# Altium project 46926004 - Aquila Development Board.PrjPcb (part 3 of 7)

## Sheet 400_M2_KeyB.SchDoc: Aquila Development Board
size A3; Organization: Toradex Solutions Inc.; Address1: 6415 Northwest Drive; Address2: Mississauga, ON, L4V 1X1; Address3: Canada; SheetNumber: 21; SheetTotal: 34
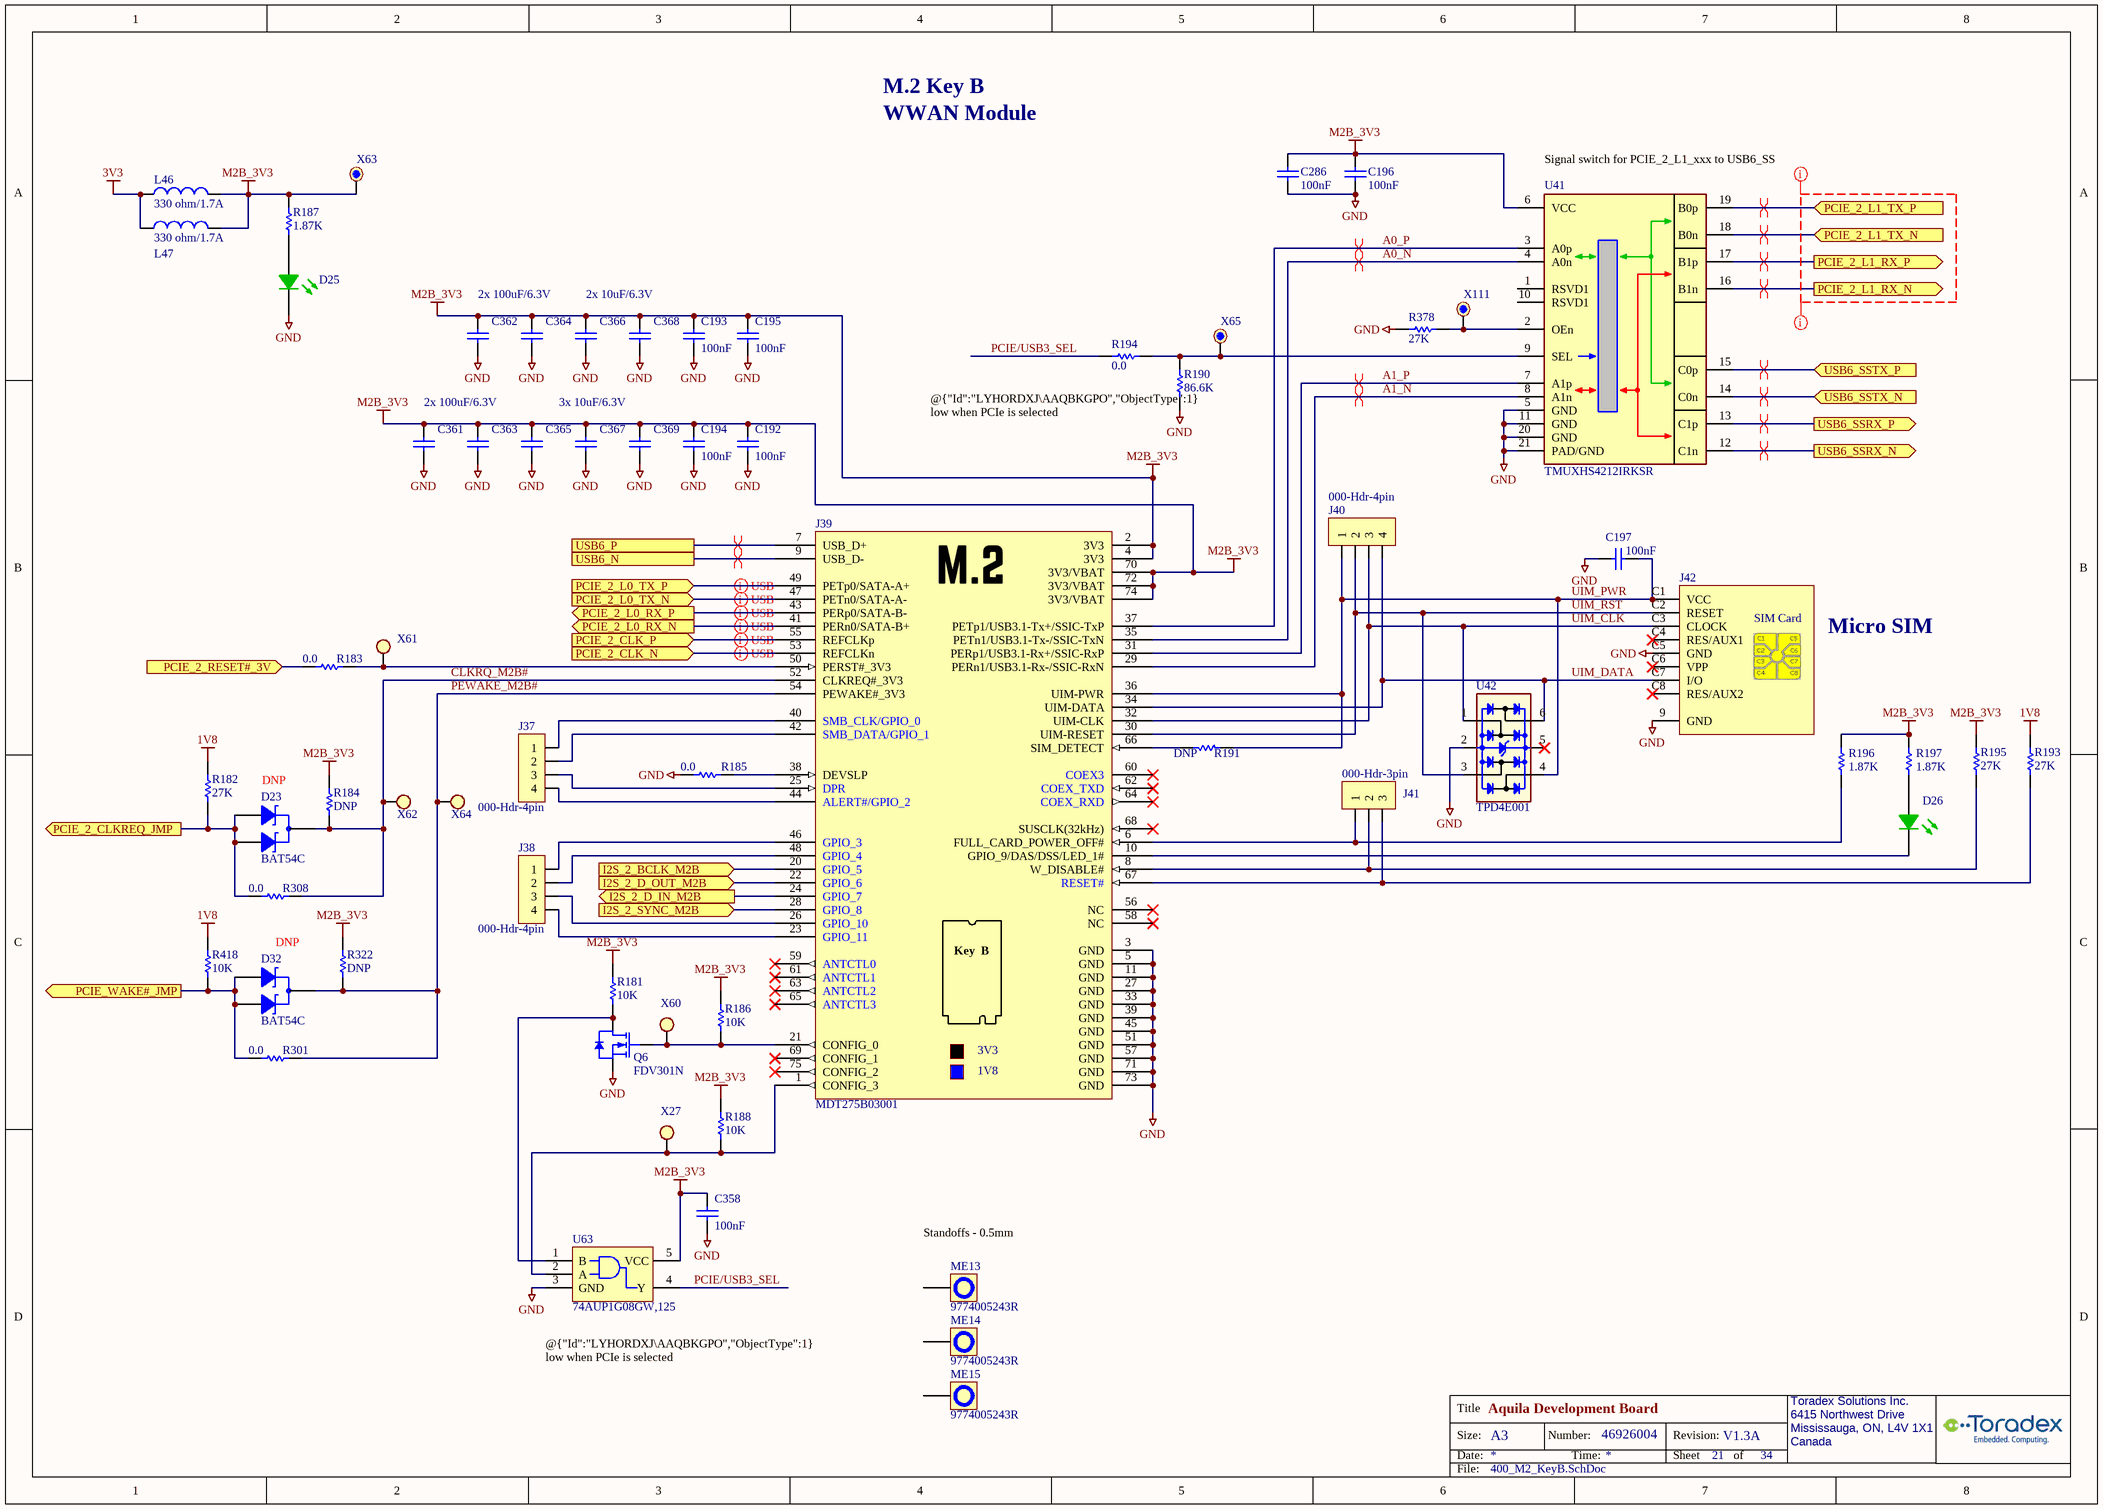
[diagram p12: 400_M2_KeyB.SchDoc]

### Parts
C192  100nF  [C0402_CAPC1005L]
C193  100nF  [C0402_CAPC1005L]
C194  100nF  [C0402_CAPC1005L]
C195  100nF  [C0402_CAPC1005L]
C196  100nF  [C0402_CAPC1005L]
C197  100nF  [C0402_CAPC1005L]
C286  100nF  [C0402_CAPC1005L]
C358  100nF  [C0402_CAPC1005L]
C361  0455-Cap-1206-100uF/6.3V  [C/1206]  (value not drawn)
C362  0455-Cap-1206-100uF/6.3V  [C/1206]  (value not drawn)
C363  0455-Cap-1206-100uF/6.3V  [C/1206]  (value not drawn)
C364  0455-Cap-1206-100uF/6.3V  [C/1206]  (value not drawn)
C365  1646-Cap-0402-10uF/6.3V  [C0402_CAPC1005L]  (value not drawn)
C366  1646-Cap-0402-10uF/6.3V  [C0402_CAPC1005L]  (value not drawn)
C367  1646-Cap-0402-10uF/6.3V  [C0402_CAPC1005L]  (value not drawn)
C368  1646-Cap-0402-10uF/6.3V  [C0402_CAPC1005L]  (value not drawn)
C369  1646-Cap-0402-10uF/6.3V  [C0402_CAPC1005L]  (value not drawn)
D23  BAT54C  [SOT23_M]  (no BOM)
D25  Status  [LED-SMT-0603_APT1608CGCK]  (value not drawn)
D26  Status  [LED-SMT-0603_APT1608CGCK]  (value not drawn)
D32  BAT54C  [SOT23_M]  (no BOM)
J37  000-Hdr-4pin  [HDR1X4]  (no BOM)
J38  000-Hdr-4pin  [HDR1X4]  (no BOM)
J39  MDT275B03001  [AMPHENOL_MDT275B03001_TYPE_3052]
J40  000-Hdr-4pin  [HDR1X4]  (no BOM)
J41  000-Hdr-3pin  [HDR1X3]  (no BOM)
J42  0737-Conn-MicroSIM  [microSD 0787231001]  (value not drawn)
L46  value 330 ohm/1.7A  [C/0603]  (hidden comment: 0405-Fer-0603-330ohm/1.7A)
L47  value 330 ohm/1.7A  [C/0603]  (hidden comment: 0405-Fer-0603-330ohm/1.7A)
ME13  9774005243R  [MECH-WURTH-9774005243R]
ME14  9774005243R  [MECH-WURTH-9774005243R]
ME15  9774005243R  [MECH-WURTH-9774005243R]
Q6  FDV301N  [SOT23]
R181  value 10K  [R0402_RESC1005L]  (hidden comment: 1572-Res-0402-10K)
R182  value 27K  [R0402_RESC1005L]  (hidden comment: 1538-Res-0402-27k)
R183  value 0.0  [R/0603]  (hidden comment: 0195-Res-0603-0.0ohm)
R184  value DNP  [R0402_RESC1005L]  (hidden comment: 0000-Res-0402-DNP)
R185  value 0.0  [R/0603]  (hidden comment: 0195-Res-0603-0.0ohm)
R186  value 10K  [R0402_RESC1005L]  (hidden comment: 1572-Res-0402-10K)
R187  value 1.87K  [R0402_RESC1005L]  (hidden comment: 1536-Res-0402-1.87K)
R188  value 10K  [R0402_RESC1005L]  (hidden comment: 1572-Res-0402-10K)
R190  value 86.6K  [R0402_RESC1005L]  (hidden comment: 1539-Res-0402-86.6k)
R191  value DNP  [R/0603]  (hidden comment: 0000-Res-0603-DNP)
R193  value 27K  [R0402_RESC1005L]  (hidden comment: 1538-Res-0402-27k)
R194  value 0.0  [R/0603]  (hidden comment: 0195-Res-0603-0.0ohm)
R195  value 27K  [R0402_RESC1005L]  (hidden comment: 1538-Res-0402-27k)
R196  value 1.87K  [R0402_RESC1005L]  (hidden comment: 1536-Res-0402-1.87K)
R197  value 1.87K  [R0402_RESC1005L]  (hidden comment: 1536-Res-0402-1.87K)
R301  value 0.0  [R/0603]  (hidden comment: 0195-Res-0603-0.0ohm)
R308  value 0.0  [R/0603]  (hidden comment: 0195-Res-0603-0.0ohm)
R322  value DNP  [R0402_RESC1005L]  (hidden comment: 0000-Res-0402-DNP)
R378  value 27K  [R0402_RESC1005L]  (hidden comment: 1538-Res-0402-27k)
R418  value 10K  [R0402_RESC1005L]  (hidden comment: 1572-Res-0402-10K)
U41  TMUXHS4212IRKSR  [VQFN-20 (4.5x2.5)]
U42  TPD4E001  [SOT23-6]
U63  74AUP1G08GW,125  [SOT353-5N]
X27  000-TestPoint2  [TestPoint_3]  (value not drawn)
X60  000-TestPoint2  [TestPoint_3]  (value not drawn)
X61  000-TestPoint2  [TestPoint_3]  (value not drawn)
X62  000-TestPoint2  [TestPoint_3]  (value not drawn)
X63  000-TestPoint  [TestPoint_1]  (value not drawn)
X64  000-TestPoint2  [TestPoint_3]  (value not drawn)
X65  000-TestPoint  [TestPoint_1]  (value not drawn)
X111  000-TestPoint  [TestPoint_1]  (value not drawn)

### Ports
I2S_2_BCLK_M2B (in), I2S_2_D_IN_M2B (out), I2S_2_D_OUT_M2B (in), I2S_2_SYNC_M2B (in), PCIE_2_CLK_N (in), PCIE_2_CLK_P (in), PCIE_2_CLKREQ_JMP (out), PCIE_2_L0_RX_N (out), PCIE_2_L0_RX_P (out), PCIE_2_L0_TX_N (in), PCIE_2_L0_TX_P (in), PCIE_2_L1_RX_N (out), PCIE_2_L1_RX_P (out), PCIE_2_L1_TX_N (in), PCIE_2_L1_TX_P (in), PCIE_2_RESET#_3V (in), PCIE_WAKE#_JMP (out), USB6_N, USB6_P, USB6_SSRX_N (out), USB6_SSRX_P (out), USB6_SSTX_N (in), USB6_SSTX_P (in)

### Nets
1V8: R182.1 R193.1 R418.2
3V3: L46.1 L47.1
GND: C192.1 C193.1 C194.1 C195.1 C196.2 C197.2 C286.2 C358.1 C361.1 C362.1 C363.1 C364.1 C365.1 C366.1 C367.1 C368.1 C369.1 D25.2(K) J39.3(GND) J39.5(GND) J39.11(GND) J39.27(GND) J39.33(GND) J39.39(GND) J39.45(GND) J39.51(GND) J39.57(GND) J39.71(GND) J39.73(GND) J42.9(GND) J42.C5(GND) Q6.2(S) R185.2 R190.1 R378.1 U41.5(GND) U41.11(GND) U41.20(GND) U41.21(PAD/GND) U42.2 U63.3(GND)
M2B_3V3: C192.2 C193.2 C194.2 C195.2 C196.1 C286.1 C358.2 C361.2 C362.2 C363.2 C364.2 C365.2 C366.2 C367.2 C368.2 C369.2 J39.2(3V3) J39.4(3V3) J39.70(3V3/VBAT) J39.72(3V3/VBAT) J39.74(3V3/VBAT) L46.2 L47.2 R181.2 R184.1 R186.2 R187.2 R188.2 R195.1 R196.2 R197.2 R322.1 U41.6(VCC) U63.5(VCC) X63.1
A0_N: J39.35(PETn1/USB3.1-Tx-/SSIC-TxN) U41.4(A0n)
A0_P: J39.37(PETp1/USB3.1-Tx+/SSIC-TxP) U41.3(A0p)
A1_N: J39.29(PERn1/USB3.1-Rx-/SSIC-RxN) U41.8(A1n)
A1_P: J39.31(PERp1/USB3.1-Rx+/SSIC-RxP) U41.7(A1p)
CLKRQ_M2B#: D23.3(K) J39.52(CLKREQ#_3V3) R184.2 R308.2 X62.1
I2S_2_BCLK_M2B: J39.20(GPIO_5) ; port I2S_2_BCLK_M2B
I2S_2_D_IN_M2B: J39.24(GPIO_7) ; port I2S_2_D_IN_M2B
I2S_2_D_OUT_M2B: J39.22(GPIO_6) ; port I2S_2_D_OUT_M2B
I2S_2_SYNC_M2B: J39.28(GPIO_8) ; port I2S_2_SYNC_M2B
PCIE/USB3_SEL: R194.2 U63.4(Y)
PCIE_2_CLK_N: J39.53(REFCLKn) ; port PCIE_2_CLK_N
PCIE_2_CLK_P: J39.55(REFCLKp) ; port PCIE_2_CLK_P
PCIE_2_CLKREQ_JMP: D23.1(A1) D23.2(A2) R182.2 R308.1 ; port PCIE_2_CLKREQ_JMP
PCIE_2_L0_RX_N: J39.41(PERn0/SATA-B+) ; port PCIE_2_L0_RX_N
PCIE_2_L0_RX_P: J39.43(PERp0/SATA-B-) ; port PCIE_2_L0_RX_P
PCIE_2_L0_TX_N: J39.47(PETn0/SATA-A-) ; port PCIE_2_L0_TX_N
PCIE_2_L0_TX_P: J39.49(PETp0/SATA-A+) ; port PCIE_2_L0_TX_P
PCIE_2_L1_RX_N: U41.16(B1n) ; port PCIE_2_L1_RX_N
PCIE_2_L1_RX_P: U41.17(B1p) ; port PCIE_2_L1_RX_P
PCIE_2_L1_TX_N: U41.18(B0n) ; port PCIE_2_L1_TX_N
PCIE_2_L1_TX_P: U41.19(B0p) ; port PCIE_2_L1_TX_P
PCIE_2_RESET#_3V: R183.1 ; port PCIE_2_RESET#_3V
PCIE_WAKE#_JMP: D32.1(A1) D32.2(A2) R301.1 R418.1 ; port PCIE_WAKE#_JMP
PEWAKE_M2B#: D32.3(K) J39.54(PEWAKE#_3V3) R301.2 R322.2 X64.1
UIM_CLK: J39.32(UIM-CLK) J40.3 J42.C3(CLOCK) U42.1
UIM_DATA: J39.34(UIM-DATA) J40.4 J42.C7(I/O) U42.6
UIM_PWR: C197.1 J39.36(UIM-PWR) J40.1 J42.C1(VCC) R191.1 U42.4
UIM_RST: J39.30(UIM-RESET) J40.2 J42.C2(RESET) U42.3
USB6_N: J39.9(USB_D-) ; port USB6_N
USB6_P: J39.7(USB_D+) ; port USB6_P
USB6_SSRX_N: U41.12(C1n) ; port USB6_SSRX_N
USB6_SSRX_P: U41.13(C1p) ; port USB6_SSRX_P
USB6_SSTX_N: U41.14(C0n) ; port USB6_SSTX_N
USB6_SSTX_P: U41.15(C0p) ; port USB6_SSTX_P
NetD25_1: D25.1(A) R187.1
NetD26_1: D26.1(A) R197.1
NetD26_2: D26.2(K) J39.10(GPIO_9/DAS/DSS/LED_1#)
NetJ37_1: J37.1 J39.40(SMB_CLK/GPIO_0)
NetJ37_2: J37.2 J39.42(SMB_DATA/GPIO_1)
NetJ37_3: J37.3 J39.25(DPR)
NetJ37_4: J37.4 J39.44(ALERT#/GPIO_2)
NetJ38_1: J38.1 J39.46(GPIO_3)
NetJ38_2: J38.2 J39.48(GPIO_4)
NetJ38_3: J38.3 J39.26(GPIO_10)
NetJ38_4: J38.4 J39.23(GPIO_11)
NetJ39_1: J39.1(CONFIG_3) R188.1 U63.2(A) X27.1
NetJ39_6: J39.6(FULL_CARD_POWER_OFF#) J41.1 R196.1
NetJ39_8: J39.8(W_DISABLE#) J41.2 R195.2
NetJ39_21: J39.21(CONFIG_0) Q6.1(G) R186.1 X60.1
NetJ39_38: J39.38(DEVSLP) R185.1
NetJ39_50: J39.50(PERST#_3V3) R183.2 X61.1
NetJ39_66: J39.66(SIM_DETECT) R191.2
NetJ39_67: J39.67(RESET#) J41.3 R193.2
NetQ6_3: Q6.3(D) R181.1 U63.1(B)
NetR190_2: R190.2 R194.1 U41.9(SEL) X65.1
NetR378_2: R378.2 U41.2(OEn) X111.1

Not connected (* = marked no-connect by the designer): J39 56(NC)* 58(NC)* 59(ANTCTL0)* 60(COEX3)* 61(ANTCTL1)* 62(COEX_TXD)* 63(ANTCTL2)* 64(COEX_RXD)* 65(ANTCTL3)* 68(SUSCLK(32kHz))* 69(CONFIG_1)* 75(CONFIG_2)*; J42 C4(RES/AUX1)* C6(VPP)* C8(RES/AUX2)*; ME13 0; ME14 0; ME15 0; U41 1(RSVD1) 10(RSVD1); U42 5*

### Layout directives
differential pair: PCIE_2_CLK_N, PCIE_2_CLK_P, PCIE_2_L0_RX_N, PCIE_2_L0_RX_P, PCIE_2_L0_TX_N, PCIE_2_L0_TX_P, USB6_N, USB6_P
Diff. Impedance: 85: (no net found under the mark)
Sing. Impedance: 42.5: (no net found under the mark)
differential pair; differential pair class USB_6_SSTX: USB6_SSTX_N, USB6_SSTX_P
differential pair; differential pair class USB_6_SSRX: USB6_SSRX_N, USB6_SSRX_P
differential pair; differential pair class PCIe_2: PCIE_2_L1_RX_N, PCIE_2_L1_RX_P, PCIE_2_L1_TX_N, PCIE_2_L1_TX_P
differential pair; differential pair class PCIEUSB: A0_N, A0_P, A1_N, A1_P

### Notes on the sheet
- M.2 Key B
- WWAN Module
- (near U41) Signal switch for PCIE_2_L1_xxx to USB6_SS
- 2x 100uF/6.3V
- 2x 10uF/6.3V
- 3x 10uF/6.3V
- @{"Id":"LYHORDXJ\AAQBKGPO","ObjectType":1} low when PCIe is selected
  @{"Id":"LYHORDXJ\AAQBKGPO","ObjectType":1} high when USB3 selected
- Micro SIM
- (near D23) DNP
- DNP
- (near ME13) Standoffs - 0.5mm
- (near U63) @{"Id":"LYHORDXJ\AAQBKGPO","ObjectType":1} low when PCIe is selected
  @{"Id":"LYHORDXJ\AAQBKGPO","ObjectType":1} high when USB3 selected

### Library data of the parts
C192-C197 C286 C358 = 1566-Cap-0402-100nF/50V: (-55 to 125 DegC AEC) Cap Ceramic 0.1uF 50V X7R 10% 0402; MfrNo: GRT155R71H104KE01D; Mfr: Murata; Alt: CL05B104KB54PNC,GCM155R71H104ME02D,GCM155R71H104KE02D,GCM155R71H104KE02J; PN: 1566
C361-C364 = 0455-Cap-1206-100uF/6.3V: (-55 to 85 DegC) CAP CER 100UF 6.3V X5R 1206; Mfr: Yageo; MfrNo: CC1206MKX5R5BB107; PN: 455; Alt: 490-7217-1-ND; Alt2: 490-4539-1-ND; DR: 311-1991-6-ND; TR: 311-1991-2-ND
C365-C369 = 1646-Cap-0402-10uF/6.3V: (-55 to 85 DegC) CAP CER 10UF 6.3V 20% X5R 0402; Mfr: Murata; MfrNo: GRM155R60J106ME44D; PN: 1646; Alt: GRM155R60J106ME47D,C0402C106M9PACTU,04026D106MAT2A
D23 D32 = 0242B-BAT54C: (-55 to 125 DegC) DIODE SCHOTTKY 30V 200MA SOT23, comm. Cathode; Mfr: ON Semi; MfrNo: BAT54CLT1G; Alt: BAT54CFSCT-ND; Alt2: BAT54C-FDICT-ND; PN: 242; TR: BAT54CLT1GOSTR-ND; DR: BAT54CLT1GOSDKR-ND; DR2: 863-BAT54CLT1G
D25 D26 = 0333-LED Green 0603: (-40 to 85 DegC) LED GREEN 0603 50mcd; MfrNo: APT1608CGCK; Mfr: Kingbright; Alt: 754-1357-1-ND; Alt2: 160-1834-1-ND; PN: 333; DR: 754-1116-6-ND; DR2: 604-APT1608CGCK
J37 J38 J40 = 000-Hdr-4pin: Header, 4-Pin; Note: PCB footprint only, no parts to buy or assemble
J39 = 2186-Conn-M2-KeyB: (-40 to 80 DegC) CONN M2 M.2 Key B 67pos H=2.75mm Gold; Mfr: Amphenol Commercial; PN: 2186
J41 = 000-Hdr-3pin: Header, 3-Pin; Note: PCB footprint only, no parts to buy or assemble
J42 = 0737-Conn-MicroSIM: (-40 to 85 DegC) CONN MICRO SIM CARD PUSH-PULL; MfrNo: 0787231001; Mfr: Molex, LLC; PN: 737; DR: WM9259DKR-ND
L46 L47 = 0405-Fer-0603-330ohm/1.7A: (-55 to 125 DegC) FERRITE BEAD 330 OHM 0603 1.7A 80mohm, typ 48mohm; Mfr: TDK Corporation; MfrNo: MPZ1608S331ATA00; PN: 405; TR: 445-5221-2-ND; DR: 445-5221-6-ND; DR2: 810-MPZ1608S331ATA00
ME13-ME15 = 1855-Post-M2-0.5mm: (-55 to 155 DegC) ROUND STANDOFF M2X0.4 STEEL 0.5MM; Mfr: Wurth Electronics; PN: 1855
Q6 = 0761-FDV301N: (-55 to 155 DegC) MOSFET N-CH 25V 220MA SOT-23 Vth:1.1V Ron typ:4ohm@3V Vgsm:8V; Mfr: Fairchild/ON Semiconductor; PN: 761; DR: FDV301NDKR-ND; TR: FDV301NTR-ND; Alt: DMN62D0U-13, DMN62D0U-7, DMN61D9U-7
R181 R186 R188 R418 = 1572-Res-0402-10K: (-55 to 155 DegC AEC) RES 10K OHM 1% 1/16W 100ppm 0402; Mfr: Stackpole Electronics; MfrNo: RMCF0402FT10K0; Alt: AC0402FR-0710KL,AC0402FR-1310KL,CRGCQ0402F10K; PN: 1572
R182 R193 R195 R378 = 1538-Res-0402-27k: (-55 to 155 DegC AEC) RES 27K OHM 1% 1/16W 100ppm 0402; Mfr: Stackpole Electronics; MfrNo: RMCF0402FT27K0; PN: 1538; Alt: AC0402FR-0727KL,CRGCQ0402F27K
R183 R185 R194 R301 R308 = 0195-Res-0603-0.0ohm: (-55 to 155 DegC) RES 0.0 OHM 1/10W JUMP 0603; Mfr: Samsung; MfrNo: RC1608J000CS; Alt: 311-0.0GRCT-ND; Alt2: A106051CT-ND; PN: 195; TR: 1276-3510-2-ND
R184 R322 = 0000-Res-0402-DNP: RES 0402
R187 R196 R197 = 1536-Res-0402-1.87K: (-55 to 155 DegC AEC) RES 1.87K OHM 1% 1/16W 100ppm 0402; MfrNo: RMCF0402FT1K87; Mfr: Stackpole Electronics; Alt: AC0402FR-071K87L,RK73H1ETTP1871F,ERJ-2RKF1871X; PN: 1536
R190 = 1539-Res-0402-86.6k: (-55 to 155 DegC AEC) RES 86.6K OHM 1% 1/16W 100ppm 0402; Mfr: Stackpole Electronics; MfrNo: RMCF0402FT86K6; Alt: AC0402FR-0786K6L,RK73H1ETTP8662F,ERJ-2RKF8662X; PN: 1539
R191 = 0000-Res-0603-DNP: RES 0603
U41 = 2263-TMUXHS4212IRKSR: (-40 to 105 DegC) IC SWITCH MULTIPLEXER 2:1 DPST, SPDT X 2 3.3V/1.8V 20VQFN; Mfr: Texas Instruments; PN: 2263
U42 = 0740-TPD4E001: (-40 to 125 DegC AEC) TVS DIODE 5.5VWM 16VC SOT-23-6; MfrNo: TPD4E001QDBVRQ1; Mfr: Texas Instruments; PN: 740; Alt: TPD4E001DBVR
U63 = 1864-74AUP1G08GW: (-40 to 125 DegC) IC GATE AND 1CH 2-INP 0.8-3.6V 5-TSSOP; Mfr: Nexperia; PN: 1864
X27 X60-X62 X64 = 000-TestPoint2: TestPoint SMD; Note: PCB footprint only, no parts to buy or assemble
X63 X65 X111 = 000-TestPoint: TestPoint TH; Note: this is PCB footprint only, no parts to buy or assemble

## Sheet 420_MIPI_DSI.SchDoc: Aquila Development Board
size Letter; Organization: Toradex Solutions Inc.; Address1: 6415 Northwest Drive; Address2: Mississauga, ON, L4V 1X1; Address3: Canada; SheetNumber: 23; SheetTotal: 34
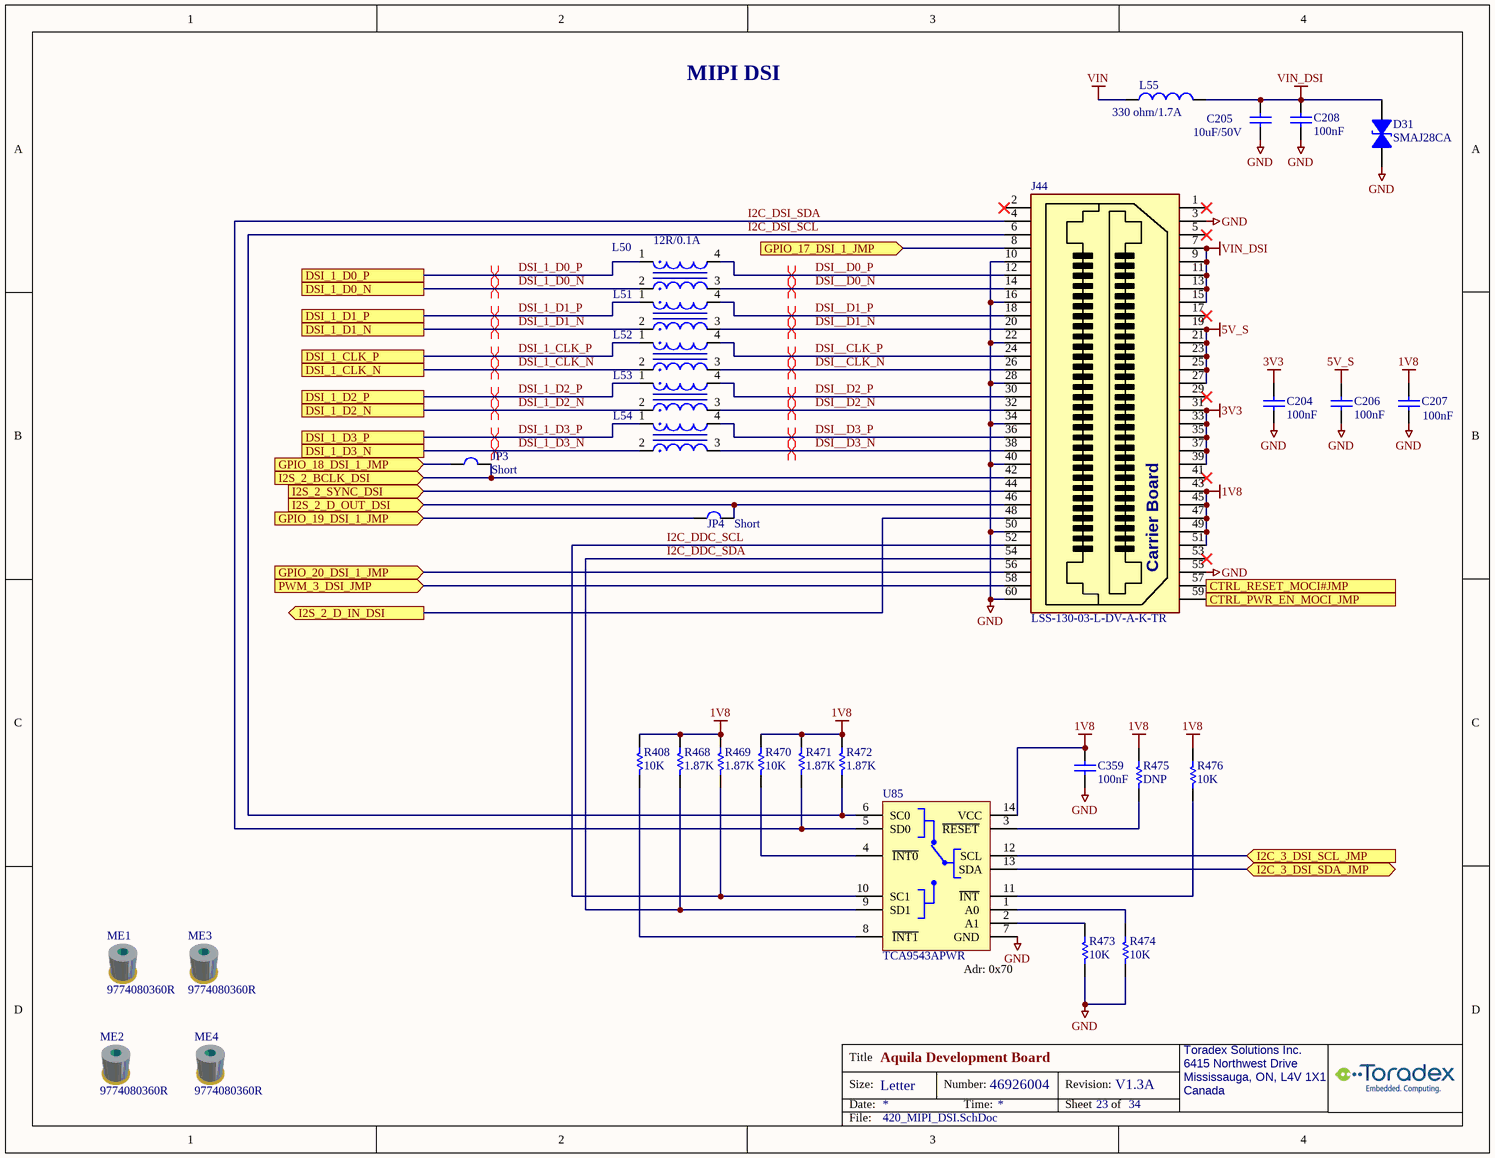
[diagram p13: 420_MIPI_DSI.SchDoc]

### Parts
C204  100nF  [C0402_CAPC1005L]
C205  10uF/50V  [CAPC3225N]
C206  100nF  [C0402_CAPC1005L]
C207  100nF  [C0402_CAPC1005L]
C208  100nF  [C0402_CAPC1005L]
C359  100nF  [C0402_CAPC1005L]
D31  SMAJ28CA  [SMAJ_TRANSIL]
J44  LSS-130-03-L-DV-A-K-TR  [SAMTEC_LSS-130-03-L-DV-A-K-TR_ALT]
JP3  Short  [Short_040]  (net tie, no BOM)
JP4  Short  [Short_040]  (net tie, no BOM)
L50  12R/0.1A  [COIL0302]
L51  12R/0.1A  [COIL0302]  (value not drawn)
L52  12R/0.1A  [COIL0302]  (value not drawn)
L53  12R/0.1A  [COIL0302]  (value not drawn)
L54  12R/0.1A  [COIL0302]  (value not drawn)
L55  value 330 ohm/1.7A  [C/0603]  (hidden comment: 0405-Fer-0603-330ohm/1.7A)
ME1  9774080360R  [WURTH_9774080360R]
ME2  9774080360R  [WURTH_9774080360R]
ME3  9774080360R  [WURTH_9774080360R]
ME4  9774080360R  [WURTH_9774080360R]
R408  value 10K  [R0402_RESC1005L]  (hidden comment: 1572-Res-0402-10K)
R468  value 1.87K  [R0402_RESC1005L]  (hidden comment: 1536-Res-0402-1.87K)
R469  value 1.87K  [R0402_RESC1005L]  (hidden comment: 1536-Res-0402-1.87K)
R470  value 10K  [R0402_RESC1005L]  (hidden comment: 1572-Res-0402-10K)
R471  value 1.87K  [R0402_RESC1005L]  (hidden comment: 1536-Res-0402-1.87K)
R472  value 1.87K  [R0402_RESC1005L]  (hidden comment: 1536-Res-0402-1.87K)
R473  value 10K  [R0402_RESC1005L]  (hidden comment: 1572-Res-0402-10K)
R474  value 10K  [R0402_RESC1005L]  (hidden comment: 1572-Res-0402-10K)
R475  value DNP  [R0402_RESC1005L]  (hidden comment: 0000-Res-0402-DNP)
R476  value 10K  [R0402_RESC1005L]  (hidden comment: 1572-Res-0402-10K)
U85  TCA9543APWR  [TSSOP14]

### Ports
CTRL_PWR_EN_MOCI_JMP (in), CTRL_RESET_MOCI#JMP (in), DSI_1_CLK_N, DSI_1_CLK_P, DSI_1_D0_N, DSI_1_D0_P, DSI_1_D1_N, DSI_1_D1_P, DSI_1_D2_N, DSI_1_D2_P, DSI_1_D3_N, DSI_1_D3_P, GPIO_17_DSI_1_JMP (in), GPIO_18_DSI_1_JMP (in), GPIO_19_DSI_1_JMP (in), GPIO_20_DSI_1_JMP (in), I2C_3_DSI_SCL_JMP (in), I2C_3_DSI_SDA_JMP (bidir), I2S_2_BCLK_DSI (in), I2S_2_D_IN_DSI (out), I2S_2_D_OUT_DSI (in), I2S_2_SYNC_DSI (in), PWM_3_DSI_JMP (in)

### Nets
1V8: C207.2 C359.2 J44.43 J44.45 J44.47 J44.49 J44.51 R408.2 R468.2 R469.2 R470.2 R471.2 R472.2 R475.2 R476.2 U85.14(VCC)
3V3: C204.2 J44.31 J44.33 J44.35 J44.37 J44.39
5V_S: C206.2 J44.19 J44.21 J44.23 J44.25 J44.27
GND: C204.1 C205.1 C206.1 C207.1 C208.1 C359.1 D31.1 J44.3 J44.10 J44.16 J44.22 J44.28 J44.34 J44.40 J44.50 J44.55 J44.60 R473.2 R474.2 U85.7(GND)
VIN: L55.2
VIN_DSI: C205.2 C208.2 D31.2 J44.7 J44.9 J44.11 J44.13 J44.15 L55.1
CTRL_PWR_EN_MOCI_JMP: J44.59 ; port CTRL_PWR_EN_MOCI_JMP
CTRL_RESET_MOCI#JMP: J44.57 ; port CTRL_RESET_MOCI#JMP
DSI_1_CLK_N: L52.2 ; port DSI_1_CLK_N
DSI_1_CLK_P: L52.1 ; port DSI_1_CLK_P
DSI_1_D0_N: L50.2 ; port DSI_1_D0_N
DSI_1_D0_P: L50.1 ; port DSI_1_D0_P
DSI_1_D1_N: L51.2 ; port DSI_1_D1_N
DSI_1_D1_P: L51.1 ; port DSI_1_D1_P
DSI_1_D2_N: L53.2 ; port DSI_1_D2_N
DSI_1_D2_P: L53.1 ; port DSI_1_D2_P
DSI_1_D3_N: L54.2 ; port DSI_1_D3_N
DSI_1_D3_P: L54.1 ; port DSI_1_D3_P
DSI__CLK_N: J44.26 L52.3
DSI__CLK_P: J44.24 L52.4
DSI__D0_N: J44.14 L50.3
DSI__D0_P: J44.12 L50.4
DSI__D1_N: J44.20 L51.3
DSI__D1_P: J44.18 L51.4
DSI__D2_N: J44.32 L53.3
DSI__D2_P: J44.30 L53.4
DSI__D3_N: J44.38 L54.3
DSI__D3_P: J44.36 L54.4
GPIO_17_DSI_1_JMP: J44.8 ; port GPIO_17_DSI_1_JMP
GPIO_18_DSI_1_JMP: JP3.2(C2) ; port GPIO_18_DSI_1_JMP
GPIO_19_DSI_1_JMP: JP4.2(C2) ; port GPIO_19_DSI_1_JMP
GPIO_20_DSI_1_JMP: J44.56 ; port GPIO_20_DSI_1_JMP
I2C_3_DSI_SCL_JMP: U85.12(SCL) ; port I2C_3_DSI_SCL_JMP
I2C_3_DSI_SDA_JMP: U85.13(SDA) ; port I2C_3_DSI_SDA_JMP
I2C_DDC_SCL: J44.52 R469.1 U85.10(SC1)
I2C_DDC_SDA: J44.54 R468.1 U85.9(SD1)
I2C_DSI_SCL: J44.6 R472.1 U85.6(SC0)
I2C_DSI_SDA: J44.4 R471.1 U85.5(SD0)
I2S_2_BCLK_DSI: J44.42 JP3.1(C1) ; port I2S_2_BCLK_DSI
I2S_2_D_IN_DSI: J44.48 ; port I2S_2_D_IN_DSI
I2S_2_D_OUT_DSI: J44.46 JP4.1(C1) ; port I2S_2_D_OUT_DSI
I2S_2_SYNC_DSI: J44.44 ; port I2S_2_SYNC_DSI
PWM_3_DSI_JMP: J44.58 ; port PWM_3_DSI_JMP
NetR408_1: R408.1 U85.8(~{INT1})
NetR470_1: R470.1 U85.4(~{INT0})
NetR473_1: R473.1 U85.2(A1)
NetR474_1: R474.1 U85.1(A0)
NetR475_1: R475.1 U85.3(~{RESET})
NetR476_1: R476.1 U85.11(~{INT})

Not connected (* = marked no-connect by the designer): J44 1* 2* 5* 17* 29* 41* 53*

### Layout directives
differential pair; differential pair class DSI_1_CON: DSI__CLK_N, DSI__CLK_P, DSI__D0_N, DSI__D0_P, DSI__D1_N, DSI__D1_P, DSI__D2_N, DSI__D2_P, DSI__D3_N, DSI__D3_P
differential pair; differential pair class DSI_1: DSI_1_CLK_N, DSI_1_CLK_P, DSI_1_D0_N, DSI_1_D0_P, DSI_1_D1_N, DSI_1_D1_P, DSI_1_D2_N, DSI_1_D2_P, DSI_1_D3_N, DSI_1_D3_P

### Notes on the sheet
- MIPI DSI
- (near U85) Adr: 0x70

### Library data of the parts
C204 C206-C208 C359 = 1566-Cap-0402-100nF/50V: as C192-C197 on sheet 400_M2_KeyB
C205 = 1607-Cap-1206-10uF/50V: (-55 to 85 DegC) CAP CER 10UF 50V 10% X5R 1206; Mfr: Samsung; MfrNo: CL31A106KBHNNNE; Alt: CL31A106MBHNNNE,UMK316BBJ106ML-T,UMK316BBJ106KL-T,GRT31CR61H106ME01L,MSASU31LBB5106MTNA01; PN: 1607
D31 = 0434-SMAJ28CA: (-55 to 150 DegC) TVS DIODE 28VWM 59VC SMA; Mfr: STMicroelectronics; MfrNo: SMAJ28CA-TR; PN: 434; Alt: SMAJ28CABCT-ND; Alt2: SMAJ28CA-TPMSCT-ND
J44 = 1462-Conn-SelfMate-60pin: (-55 to 125 DegC) CONN SELF-MATE 60POS SMD GOLD; Mfr: Samtec; PN: 1462; Notes: used for MIPI DSI adapters
JP3 JP4 = 000-Jumper-Short: Jumper Wire
L50-L54 = 1371-Ind-0.8x0.6-12ohm/0.1A-Choke: (-40 to 85 DegC) Ind CMC Choke 12 Ohm 0.1A 1ohm 0.85x0.65x0.5mm; MfrNo: EXC-14CH120U; Mfr: Panasonic; PN: 1371
L55 = 0405-Fer-0603-330ohm/1.7A: as L46 on sheet 400_M2_KeyB
ME1-ME4 = 0989-Post-M3-8mm: (-55 to 150 DegC) ROUND STANDOFF M3X0.5 STEEL 8MM For Apalis; Mfr: Wurth Electronics Inc.; PN: 989
R408 R470 R473 R474 R476 = 1572-Res-0402-10K: (-55 to 155 DegC AEC) RES 10K OHM 1% 1/16W 100ppm 0402; MfrNo: RMCF0402FT10K0; Mfr: Stackpole Electronics; PN: 1572; Alt: AC0402FR-0710KL,AC0402FR-1310KL,CRGCQ0402F10K
R468 R469 R471 R472 = 1536-Res-0402-1.87K: (-55 to 155 DegC AEC) RES 1.87K OHM 1% 1/16W 100ppm 0402; MfrNo: RMCF0402FT1K87; Mfr: Stackpole Electronics; PN: 1536; Alt: AC0402FR-071K87L,RK73H1ETTP1871F,ERJ-2RKF1871X
R475 = 0000-Res-0402-DNP: RES 0402
U85 = 2678-TCA9543APWR: (-40 to 85 DegC) IC I2C MUX BUS SWITCH 1:2 1.65-5.5V 400kHz; Mfr: Texas Instruments; PN: 2678

## Sheet 500_CAN.SchDoc: Aquila Development Board
size Letter; Organization: Toradex Solutions Inc.; Address1: 6415 Northwest Drive; Address2: Mississauga, ON, L4V 1X1; Address3: Canada; SheetNumber: 26; SheetTotal: 34
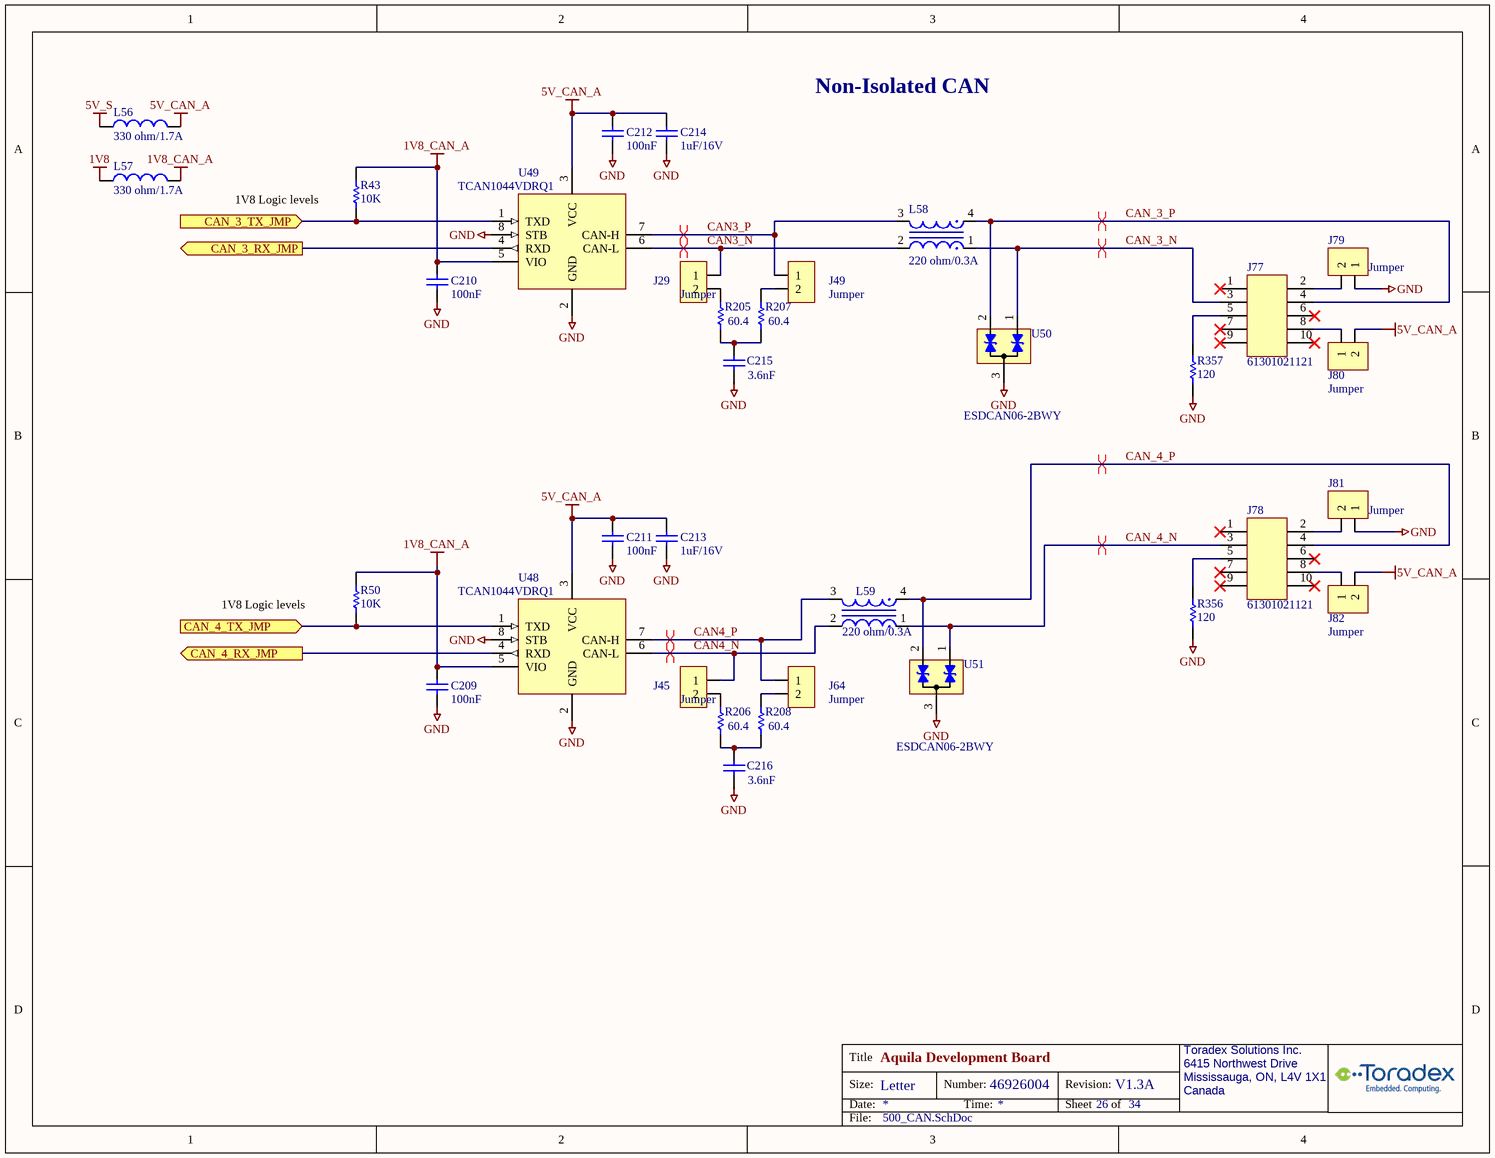
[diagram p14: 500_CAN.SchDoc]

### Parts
C209  100nF  [C0402_CAPC1005L]
C210  100nF  [C0402_CAPC1005L]
C211  100nF  [C0402_CAPC1005L]
C212  100nF  [C0402_CAPC1005L]
C213  value 1uF/16V  [C0402_CAPC1005L]  (hidden comment: 1644-Cap-0402-1uF/16V)
C214  value 1uF/16V  [C0402_CAPC1005L]  (hidden comment: 1644-Cap-0402-1uF/16V)
C215  value 3.6nF  [C/0603]  (hidden comment: 1470-Cap-0603-3.6nF)
C216  value 3.6nF  [C/0603]  (hidden comment: 1470-Cap-0603-3.6nF)
J29  67996-200HLF  [CON_HDR1X2]  (value not drawn)
J45  67996-200HLF  [CON_HDR1X2]  (value not drawn)
J49  67996-200HLF  [CON_HDR1X2]  (value not drawn)
J64  67996-200HLF  [CON_HDR1X2]  (value not drawn)
J77  61301021121  [WURTH_61301021121]
J78  61301021121  [WURTH_61301021121]
J79  67996-200HLF  [CON_HDR1X2]  (value not drawn)
J80  67996-200HLF  [CON_HDR1X2]  (value not drawn)
J81  67996-200HLF  [CON_HDR1X2]  (value not drawn)
J82  67996-200HLF  [CON_HDR1X2]  (value not drawn)
L56  value 330 ohm/1.7A  [C/0603]  (hidden comment: 0405-Fer-0603-330ohm/1.7A)
L57  value 330 ohm/1.7A  [C/0603]  (hidden comment: 0405-Fer-0603-330ohm/1.7A)
L58  220 ohm/0.3A  [COMMON_CHOKE_BOURNS_SRF2012-900YA]
L59  220 ohm/0.3A  [COMMON_CHOKE_BOURNS_SRF2012-900YA]
R43  value 10K  [R0402_RESC1005L]  (hidden comment: 1572-Res-0402-10K)
R50  value 10K  [R0402_RESC1005L]  (hidden comment: 1572-Res-0402-10K)
R205  value 60.4  [R/0603]  (hidden comment: 2199-Res-0603-60.4)
R206  value 60.4  [R/0603]  (hidden comment: 2199-Res-0603-60.4)
R207  value 60.4  [R/0603]  (hidden comment: 2199-Res-0603-60.4)
R208  value 60.4  [R/0603]  (hidden comment: 2199-Res-0603-60.4)
R356  value 120  [R0402_RESC1005L]  (hidden comment: 1552-Res-0402-120)
R357  value 120  [R0402_RESC1005L]  (hidden comment: 1552-Res-0402-120)
U48  TCAN1044VDRQ1  [SOIC-8]
U49  TCAN1044VDRQ1  [SOIC-8]
U50  ESDCAN06-2BWY  [SOT-323]
U51  ESDCAN06-2BWY  [SOT-323]

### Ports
CAN_3_RX_JMP (out), CAN_3_TX_JMP (in), CAN_4_RX_JMP (out), CAN_4_TX_JMP (in)

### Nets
1V8: L57.1
1V8_CAN_A: C209.2 C210.2 L57.2 R43.1 R50.1 U48.5(VIO) U49.5(VIO)
5V_CAN_A: C211.2 C212.2 C213.2 C214.2 J80.2 J82.2 L56.2 U48.3(VCC) U49.3(VCC)
5V_S: L56.1
GND: C209.1 C210.1 C211.1 C212.1 C213.1 C214.1 C215.2 C216.2 J79.1 J81.1 R356.2 R357.2 U48.2(GND) U48.8(STB) U49.2(GND) U49.8(STB) U50.3 U51.3
CAN3_N: J29.1 L58.2 U49.6(CAN-L)
CAN3_P: J49.1 L58.3 U49.7(CAN-H)
CAN4_N: J45.1 L59.2 U48.6(CAN-L)
CAN4_P: J64.1 L59.3 U48.7(CAN-H)
CAN_3_N: J77.3 L58.1 U50.1
CAN_3_P: J77.4 L58.4 U50.2
CAN_3_RX_JMP: U49.4(RXD) ; port CAN_3_RX_JMP
CAN_3_TX_JMP: R43.2 U49.1(TXD) ; port CAN_3_TX_JMP
CAN_4_N: J78.3 L59.1 U51.1
CAN_4_P: J78.4 L59.4 U51.2
CAN_4_RX_JMP: U48.4(RXD) ; port CAN_4_RX_JMP
CAN_4_TX_JMP: R50.2 U48.1(TXD) ; port CAN_4_TX_JMP
NetC215_1: C215.1 R205.1 R207.1
NetC216_1: C216.1 R206.1 R208.1
NetJ29_2: J29.2 R205.2
NetJ45_2: J45.2 R206.2
NetJ49_2: J49.2 R207.2
NetJ64_2: J64.2 R208.2
NetJ77_2: J77.2 J79.2
NetJ77_5: J77.5 R357.1
NetJ77_8: J77.8 J80.1
NetJ78_2: J78.2 J81.2
NetJ78_5: J78.5 R356.1
NetJ78_8: J78.8 J82.1

Not connected (* = marked no-connect by the designer): J77 1* 6* 7* 9* 10*; J78 1* 6* 7* 9* 10*

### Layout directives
differential pair; differential pair class CAN: CAN3_N, CAN3_P, CAN4_N, CAN4_P, CAN_3_N, CAN_3_P, CAN_4_N, CAN_4_P

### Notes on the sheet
- Non-Isolated CAN
- (near R43) 1V8 Logic levels
- Jumper
- (near J79) Jumper
- (near J81) Jumper
- (near R50) 1V8 Logic levels

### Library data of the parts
C209-C212 = 1566-Cap-0402-100nF/50V: as C192-C197 on sheet 400_M2_KeyB
C213 C214 = 1644-Cap-0402-1uF/16V: (-55 to 85 DegC) CAP CER 1UF 16V 20% X5R 0402; Mfr: Murata; MfrNo: GRM155R61C105MA12D; PN: 1644; Alt: GRM155R61C105KA12D,CL05A105KO5NNNC
C215 C216 = 1470-Cap-0603-3.6nF: (-55 to 125 DegC) CAP CER 3600PF 50V C0G/NP0 0603; Mfr: Murata; MfrNo: GRM1885C1H362JA01D; Alt: GCM1885C1H362FA16J,C0603C362J5GAC7867,C0603C362F5GAC7867; PN: 1470
J29 J45 J49 J64 J79-J82 = 1250-Conn-Hdr-1x2 TH Vert: (-40 to 85 DegC) CONN HDR VERT 1x2 2pos 2.54mm 0.1in Gold no-shroud; Mfr: Amphenol FCI; PN: 1250
J77 J78 = 2237-Conn-Hdr 2x10 2.54MM: (-40 to 105 DegC) CONN HEADER MALE VERT 2x5 10POS 2.54MM TH; Mfr: Wurth Electronics; PN: 2237
L56 L57 = 0405-Fer-0603-330ohm/1.7A: as L46 on sheet 400_M2_KeyB
L58 L59 = 1055-Ind-2x1.2-220ohm/0.4A-Choke: (-40 to 125 DegC) INDUCTOR COMMON MODE 220 OHM 0.3A 0.4ohm; MfrNo: SRF2012-221YA; Mfr: Bourns Inc.; PN: 1055; Alt: SRF2012-201YA
R43 R50 = 1572-Res-0402-10K: (-55 to 155 DegC AEC) RES 10K OHM 1% 1/16W 100ppm 0402; MfrNo: RMCF0402FT10K0; Mfr: Stackpole Electronics; Alt: AC0402FR-0710KL,AC0402FR-1310KL,CRGCQ0402F10K; PN: 1572
R205-R208 = 2199-Res-0603-60.4: (-55 to 155 DegC) RES SMD 60.4 OHM 1% 1/10W 0603; Mfr: Bourns; MfrNo: CR0603-FX-60R4ELF; PN: 2199; Desc: (-55 to 155 DegC) RES SMD 60.4k OHM 1% 1/10W 0603
R356 R357 = 1552-Res-0402-120: (-55 to 155 DegC AEC) RES 120 OHM 1% 1/16W 100ppm 0402; MfrNo: RMCF0402FT120R; Mfr: Stackpole Electronics; PN: 1552; Alt: AC0402FR-07120RL,CRGCQ0402F120R
U48 U49 = 1620-TCAN1044VDRQ1: (-40 to 125 DegC) IC TXRX CAN FD 8MBPS Vio:1.8-5V Standby 8SOIC; Mfr: Texas Instruments; PN: 1620
U50 U51 = 1564-ESDCAN06-2BWY: (-55 to 175 DegC AEC) TVS DIODE CAN 2-ch 35V Vcl: 59Vmax, 8/20:3A, ESD:30KV air,30KV cont, 15pF, SOT323; Mfr: STMicroelectronics; PN: 1564

## Sheet 120_Power_2.SchDoc: Aquila Development Board
size A3; Organization: Linear Computing Inc.; Address1: 6415 Northwest Drive; Address2: Mississauga, ON, L4V1X1; Address3: Canada; SheetNumber: 4; SheetTotal: 34
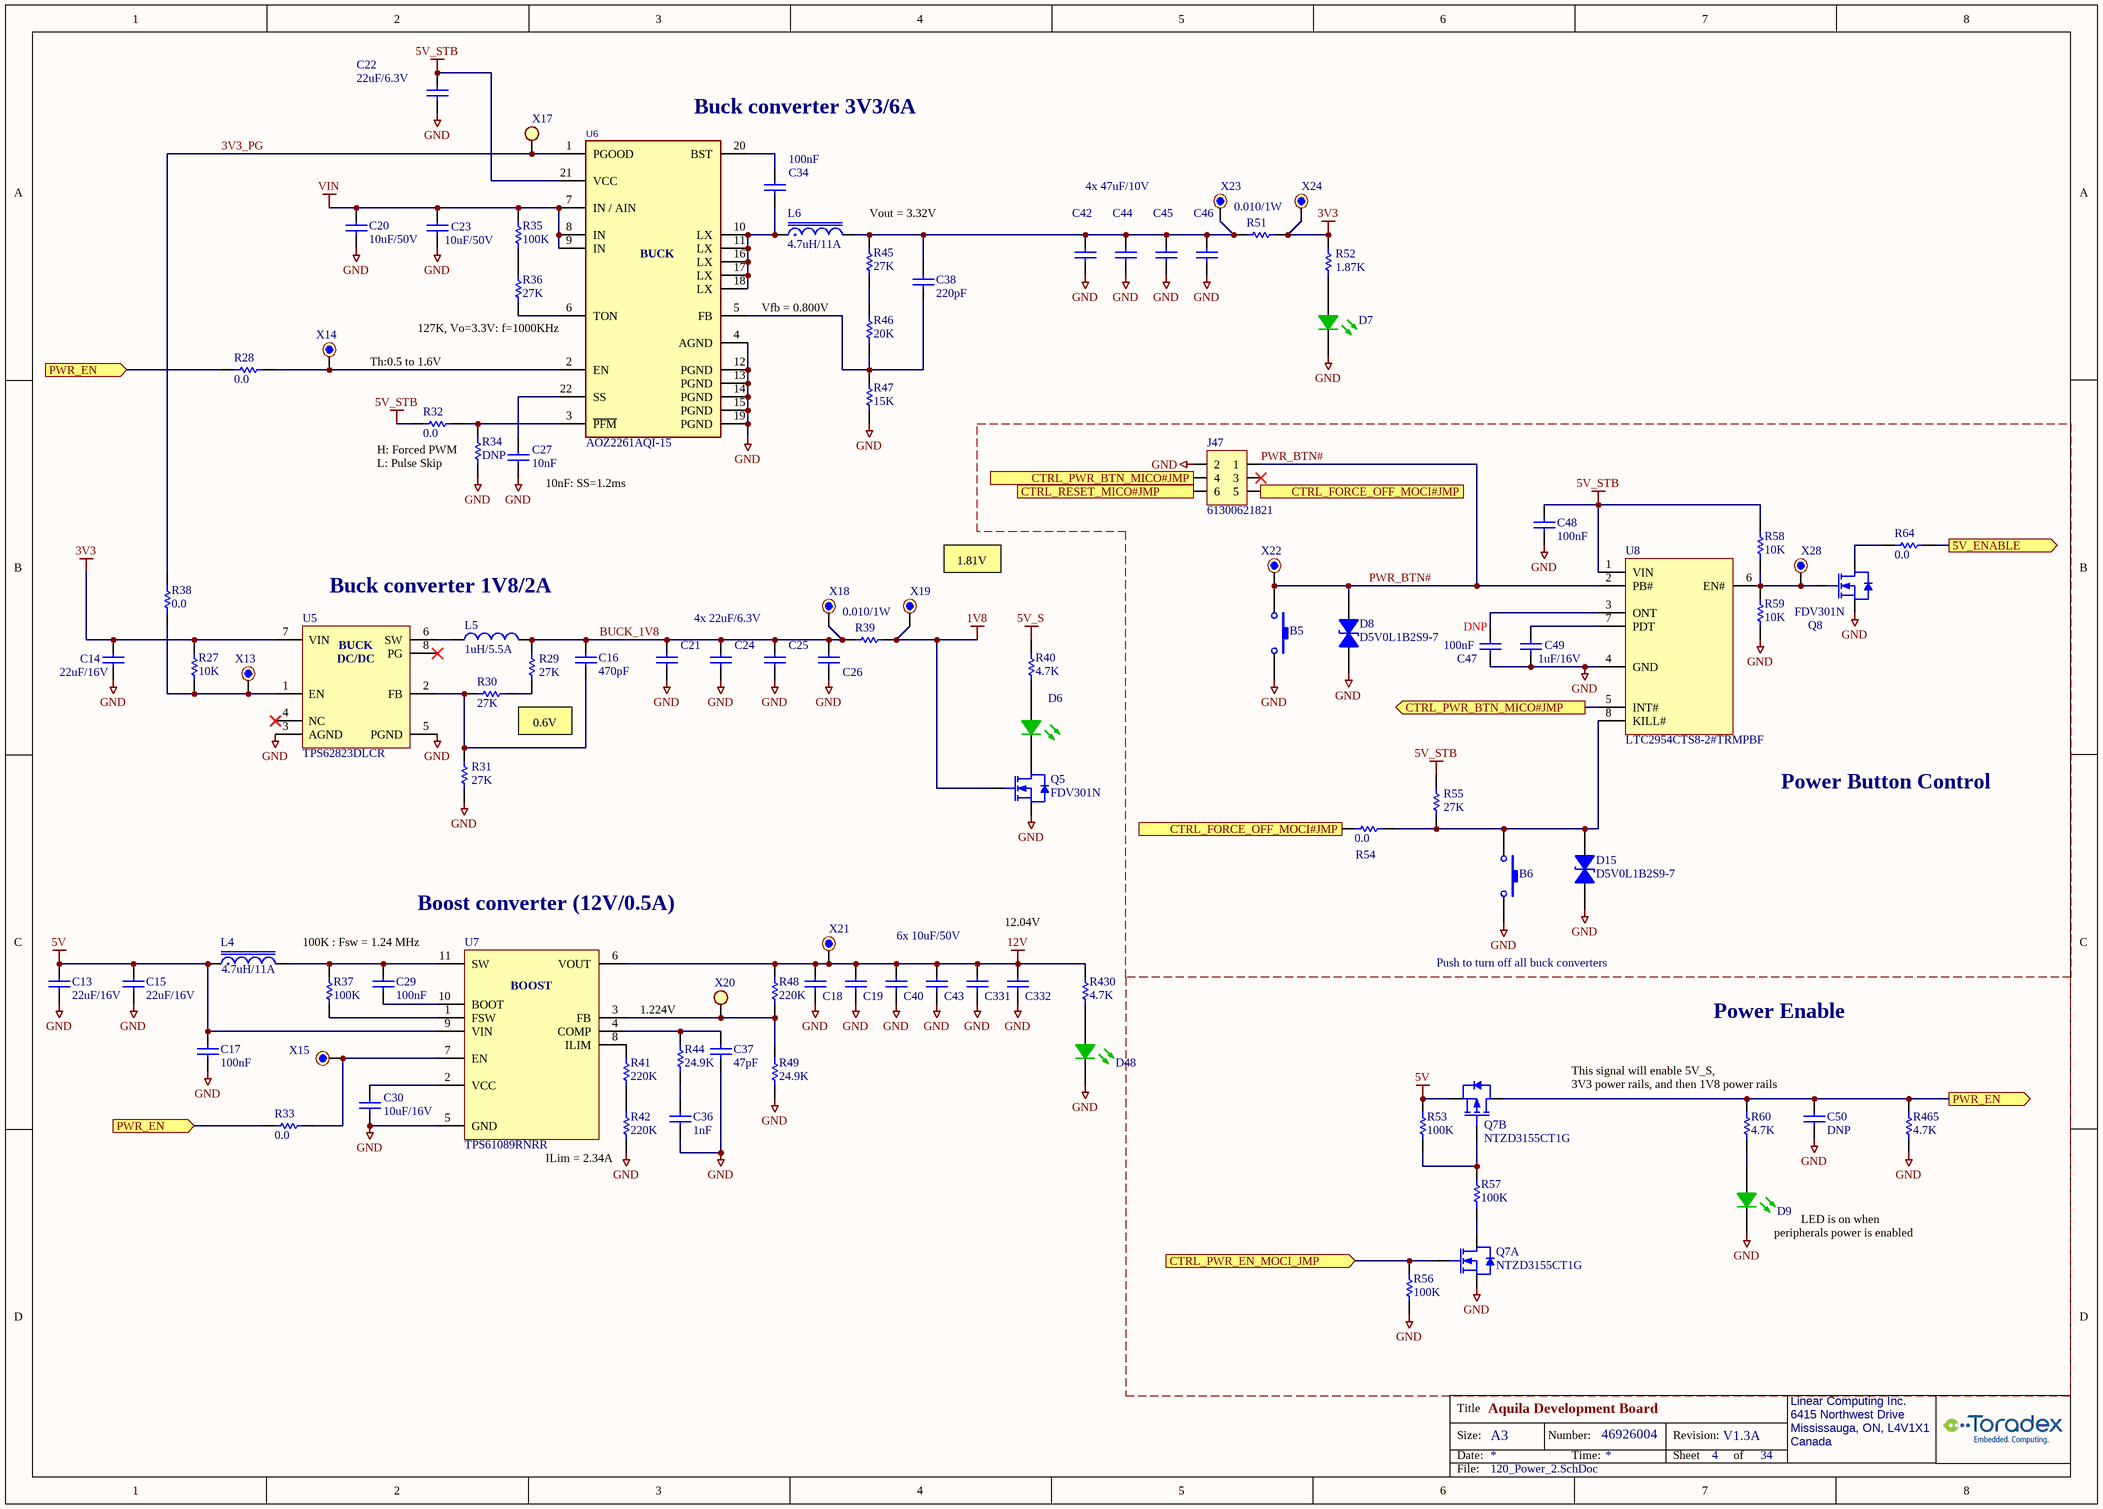
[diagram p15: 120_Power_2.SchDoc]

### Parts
B5  B3FS-1010P  [OMRONSW_B3FS-1010P]  (value not drawn)
B6  B3FS-1010P  [OMRONSW_B3FS-1010P]  (value not drawn)
C13  value 22uF/16V  [C/0805]  (hidden comment: 1314-Cap-0805-22uF/16V)
C14  value 22uF/16V  [C/0805]  (hidden comment: 1314-Cap-0805-22uF/16V)
C15  value 22uF/16V  [C/0805]  (hidden comment: 1314-Cap-0805-22uF/16V)
C16  value 470pF  [C/0603]  (hidden comment: 100nF)
C17  100nF  [C0402_CAPC1005L]
C18  10uF/50V  [CAPC3225N]  (value not drawn)
C19  10uF/50V  [CAPC3225N]  (value not drawn)
C20  10uF/50V  [CAPC3225N]
C21  22uF/6.3V  [C0402_CAPC1005L]  (value not drawn)
C22  22uF/6.3V  [C0402_CAPC1005L]
C23  10uF/50V  [CAPC3225N]
C24  22uF/6.3V  [C0402_CAPC1005L]  (value not drawn)
C25  22uF/6.3V  [C0402_CAPC1005L]  (value not drawn)
C26  22uF/6.3V  [C0402_CAPC1005L]  (value not drawn)
C27  10nF  [C0402_CAPC1005L]
C29  100nF  [C0402_CAPC1005L]
C30  value 10uF/16V  [C/0603]  (hidden comment: 2163-Cap-0603-10uF/16V)
C34  100nF  [C0402_CAPC1005L]
C36  value 1nF  [C0402_CAPC1005L]  (hidden comment: 0318-Cap-0402-1nF/50V)
C37  value 47pF  [C/0603]  (hidden comment: 1567-Cap-0603-47pF/100V)
C38  value 220pF  [C/0603]  (hidden comment: 0213-Cap-0603-220pF/50V)
C40  10uF/50V  [CAPC3225N]  (value not drawn)
C42  1647-Cap-0805-47uF/10V  [C/0805]  (value not drawn)
C43  10uF/50V  [CAPC3225N]  (value not drawn)
C44  1647-Cap-0805-47uF/10V  [C/0805]  (value not drawn)
C45  1647-Cap-0805-47uF/10V  [C/0805]  (value not drawn)
C46  1647-Cap-0805-47uF/10V  [C/0805]  (value not drawn)
C47  100nF  [C0402_CAPC1005L]  (no BOM)
C48  100nF  [C0402_CAPC1005L]
C49  value 1uF/16V  [C0402_CAPC1005L]  (hidden comment: 1644-Cap-0402-1uF/16V)
C50  value DNP  [C/0603]  (hidden comment: 0000-Cap-0603-DNP)
C331  10uF/50V  [CAPC3225N]  (value not drawn)
C332  10uF/50V  [CAPC3225N]  (value not drawn)
D6  Status  [LED-SMT-0603_APT1608CGCK]  (value not drawn)
D7  Status  [LED-SMT-0603_APT1608CGCK]  (value not drawn)
D8  D5V0L1B2S9-7  [SOD923_DIO]
D9  Status  [LED-SMT-0603_APT1608CGCK]  (value not drawn)
D15  D5V0L1B2S9-7  [SOD923_DIO]
D48  Status  [LED-SMT-0603_APT1608CGCK]  (value not drawn)
J47  61300621821  [WURTH_61300621821]
L4  value 4.7uH/11A  [EATON_EXL1V0705-4R7-R]  (hidden comment: EXL1V0705-4R7-R)
L5  value 1uH/5.5A  [INDC3225N]  (hidden comment: 1618-Ind-1210-1uH/5.5A)
L6  value 4.7uH/11A  [EATON_EXL1V0705-4R7-R]  (hidden comment: EXL1V0705-4R7-R)
Q5  FDV301N  [SOT23]
Q7  NTZD3155CT1G  [SOTFL50P160X60-6N]  (parts A,B of 2)
Q8  FDV301N  [SOT23]
R27  value 10K  [R0402_RESC1005L]  (hidden comment: 1572-Res-0402-10K)
R28  value 0.0  [R/0603]  (hidden comment: 0195-Res-0603-0.0ohm)
R29  value 27K  [R0402_RESC1005L]  (hidden comment: 1538-Res-0402-27k)
R30  value 27K  [R0402_RESC1005L]  (hidden comment: 1538-Res-0402-27k)
R31  value 27K  [R0402_RESC1005L]  (hidden comment: 1538-Res-0402-27k)
R32  value 0.0  [R/0603]  (hidden comment: 0195-Res-0603-0.0ohm)
R33  value 0.0  [R/0603]  (hidden comment: 0195-Res-0603-0.0ohm)
R34  value DNP  [R/0603]  (hidden comment: 0000-Res-0603-DNP)
R35  value 100K  [R0402_RESC1005L]  (hidden comment: 1977-Res-0402-100K)
R36  value 27K  [R0402_RESC1005L]  (hidden comment: 1538-Res-0402-27k)
R37  value 100K  [R0402_RESC1005L]  (hidden comment: 1977-Res-0402-100K)
R38  value 0.0  [R/0603]  (hidden comment: 0195-Res-0603-0.0ohm)
R39  value 0.010/1W  [R/1206]  (hidden comment: 0034-Res-1206-0.010)
R40  value 4.7K  [R0402_RESC1005L]  (hidden comment: 2233-Res-0402-4.7K)
R41  value 220K  [R/0603]  (hidden comment: 0866-Res-0603-220K)
R42  value 220K  [R/0603]  (hidden comment: 0866-Res-0603-220K)
R44  value 24.9K  [R/0603]  (hidden comment: 1144-Res-0603-24.9K)
R45  value 27K  [R0402_RESC1005L]  (hidden comment: 1538-Res-0402-27k)
R46  value 20K  [R/0603]  (hidden comment: 1216-Res-0603-20K)
R47  value 15K  [R0402_RESC1005L]  (hidden comment: 1550-Res-0402-15K)
R48  value 220K  [R/0603]  (hidden comment: 0866-Res-0603-220K)
R49  value 24.9K  [R/0603]  (hidden comment: 1144-Res-0603-24.9K)
R51  value 0.010/1W  [R/1206]  (hidden comment: 0034-Res-1206-0.010)
R52  value 1.87K  [R0402_RESC1005L]  (hidden comment: 1536-Res-0402-1.87K)
R53  value 100K  [R0402_RESC1005L]  (hidden comment: 1977-Res-0402-100K)
R54  value 0.0  [R/0603]  (hidden comment: 0195-Res-0603-0.0ohm)
R55  value 27K  [R0402_RESC1005L]  (hidden comment: 1538-Res-0402-27k)
R56  value 100K  [R0402_RESC1005L]  (hidden comment: 1977-Res-0402-100K)
R57  value 100K  [R0402_RESC1005L]  (hidden comment: 1977-Res-0402-100K)
R58  value 10K  [R0402_RESC1005L]  (hidden comment: 1572-Res-0402-10K)
R59  value 10K  [R0402_RESC1005L]  (hidden comment: 1572-Res-0402-10K)
R60  value 4.7K  [R0402_RESC1005L]  (hidden comment: 2233-Res-0402-4.7K)
R64  value 0.0  [R/0603]  (hidden comment: 0195-Res-0603-0.0ohm)
R430  value 4.7K  [R0402_RESC1005L]  (hidden comment: 2233-Res-0402-4.7K)
R465  value 4.7K  [R0402_RESC1005L]  (hidden comment: 2233-Res-0402-4.7K)
U5  TPS62823DLCR  [DLC0008A]
U6  AOZ2261AQI-15  [QFN4X4-22L_EP2_S_AOS]
U7  TPS61089RNRR  [11-VQFN-HR (2.5x2)]
U8  LTC2954CTS8-2#TRMPBF  [TSOT-23-8_ADI]
X13  000-TestPoint  [TestPoint_1]  (value not drawn)
X14  000-TestPoint  [TestPoint_1]  (value not drawn)
X15  000-TestPoint  [TestPoint_1]  (value not drawn)
X17  000-TestPoint2  [TestPoint_3]  (value not drawn)
X18  000-TestPoint  [TestPoint_1]  (value not drawn)
X19  000-TestPoint  [TestPoint_1]  (value not drawn)
X20  000-TestPoint2  [TestPoint_3]  (value not drawn)
X21  000-TestPoint  [TestPoint_1]  (value not drawn)
X22  000-TestPoint  [TestPoint_1]  (value not drawn)
X23  000-TestPoint  [TestPoint_1]  (value not drawn)
X24  000-TestPoint  [TestPoint_1]  (value not drawn)
X28  000-TestPoint  [TestPoint_1]  (value not drawn)

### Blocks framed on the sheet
Power Enable: C50 D9 Q7 R53 R56 R57 R60 R465

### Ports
5V_ENABLE (out), CTRL_FORCE_OFF_MOCI#JMP (in), CTRL_PWR_BTN_MICO#JMP (out), CTRL_PWR_EN_MOCI_JMP (in), CTRL_RESET_MICO#JMP (out), PWR_EN (in), PWR_EN (out)

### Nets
1V8: Q5.1(G) R39.2 X19.1
3V3: C14.2 R27.2 R51.2 R52.2 U5.7(VIN) X24.1
5V: C13.2 C15.2 C17.2 L4.1 Q7.4(S) R53.1 U7.9(VIN)
5V_S: R40.2
5V_STB: C22.2 C48.2 R32.1 R55.2 R58.2 U6.21(VCC) U8.1(VIN)
12V: C18.2 C19.2 C40.2 C43.2 C331.2 C332.2 R48.1 R430.2 U7.6(VOUT) X21.1
GND: B5.1 B6.1 C13.1 C14.1 C15.1 C17.1 C18.1 C19.1 C20.1 C21.1 C22.1 C23.1 C24.1 C25.1 C26.1 C27.1 C30.1 C36.1 C37.2 C40.1 C42.1 C43.1 C44.1 C45.1 C46.1 C47.1 C48.1 C49.1 C50.2 C331.1 C332.1 D7.2(K) D8.1 D9.2(K) D15.1 D48.2(K) J47.2 Q5.2(S) Q7.1(S) Q8.2(S) R31.1 R34.1 R42.2 R47.1 R49.1 R56.2 R59.1 R465.2 U5.3(AGND) U5.5(PGND) U6.4(AGND) U6.12(PGND) U6.13(PGND) U6.14(PGND) U6.15(PGND) U6.19(PGND) U7.5(GND) U8.4(GND)
VIN: C20.2 C23.2 R35.2 U6.7(IN_/_AIN) U6.8(IN) U6.9(IN)
3V3_PG: R38.2 U6.1(PGOOD) X17.1
5V_ENABLE: R64.2 ; port 5V_ENABLE
BUCK_1V8: C16.1 C21.2 C24.2 C25.2 C26.2 L5.2 R29.2 R39.1 X18.1
CTRL_FORCE_OFF_MOCI#JMP: J47.5 R54.2 ; port CTRL_FORCE_OFF_MOCI#JMP
CTRL_PWR_BTN_MICO#JMP: J47.4 U8.5(INT#) ; port CTRL_PWR_BTN_MICO#JMP
CTRL_PWR_EN_MOCI_JMP: Q7.2(G) R56.1 ; port CTRL_PWR_EN_MOCI_JMP
CTRL_RESET_MICO#JMP: J47.6 ; port CTRL_RESET_MICO#JMP
PWR_BTN#: B5.3 D8.2 J47.1 U8.2(PB#) X22.1
PWR_EN: C50.1 Q7.3(D) R28.2 R33.1 R60.1 R465.1 ; port PWR_EN
NetB6_3: B6.3 D15.2 R54.1 R55.1 U8.8(KILL#)
NetC16_2: C16.2 R30.1 R31.2 U5.2(FB)
NetC27_2: C27.2 U6.22(SS)
NetC29_1: C29.1 L4.2 R37.2 U7.11(SW)
NetC29_2: C29.2 U7.10(BOOT)
NetC30_2: C30.2 U7.2(VCC)
NetC34_1: C34.1 L6.1 U6.10(LX) U6.11(LX) U6.16(LX) U6.17(LX) U6.18(LX)
NetC34_2: C34.2 U6.20(BST)
NetC36_2: C36.2 R44.1
NetC37_1: C37.1 R44.2 U7.4(COMP)
NetC38_1: C38.1 R46.1 R47.2 U6.5(FB)
NetC38_2: C38.2 C42.2 C44.2 C45.2 C46.2 L6.2 R45.2 R51.1 X23.1
NetC47_2: C47.2 U8.3(ONT)
NetC49_2: C49.2 U8.7(PDT)
NetD6_1: D6.1(A) R40.1
NetD6_2: D6.2(K) Q5.3(D)
NetD7_1: D7.1(A) R52.1
NetD9_1: D9.1(A) R60.2
NetD48_1: D48.1(A) R430.1
NetL5_1: L5.1 U5.6(SW)
NetQ7_5: Q7.5(G) R53.2 R57.1
NetQ7_6: Q7.6(D) R57.2
NetQ8_1: Q8.1(G) R58.1 R59.2 U8.6(EN#) X28.1
NetQ8_3: Q8.3(D) R64.1
NetR27_1: R27.1 R38.1 U5.1(EN) X13.1
NetR28_1: R28.1 U6.2(EN) X14.1
NetR29_1: R29.1 R30.2
NetR32_2: R32.2 R34.2 U6.3(~{PFM})
NetR33_2: R33.2 U7.7(EN) X15.1
NetR35_1: R35.1 R36.2
NetR36_1: R36.1 U6.6(TON)
NetR37_1: R37.1 U7.1(FSW)
NetR41_1: R41.1 U7.8(ILIM)
NetR41_2: R41.2 R42.1
NetR45_1: R45.1 R46.2
NetR48_2: R48.2 R49.2 U7.3(FB) X20.1

Not connected (* = marked no-connect by the designer): J47 3*; U5 4(NC)* 8(PG)*

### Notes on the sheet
- (near U6) Buck converter 3V3/6A
- Vout = 3.32V
- 4x 47uF/10V
- Vfb = 0.800V
- Th:0.5 to 1.6V
- 127K, Vo=3.3V: f=1000KHz
- H: Forced PWM
- L: Pulse Skip
- (near C27) 10nF: SS=1.2ms
- (near X19) 1.81V
- Buck converter 1V8/2A
- 4x 22uF/6.3V
- (near C47) DNP
- 0.6V
- Power Button Control
- Boost converter (12V/0.5A)
- 100K : Fsw = 1.24 MHz
- 6x 10uF/50V
- 12.04V
- Push to turn off all buck converters
- 1.224V
- (near R60) This signal will enable 5V_S,
- 3V3 power rails, and then 1V8 power rails
- ILim = 2.34A
- (near D9) peripherals power is enabled
- LED is on when

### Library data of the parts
B5 B6 = 1511-Push Button: (-25 to 70 DegC) SWITCH TACTILE SPST-NO 0.05A 24V H:4.3mm Switch-PushButton; Mfr: Omron; PN: 1511; Alt: in bag: B3FS-1010; Note: similar to PN243 but taller
C13-C15 = 1314-Cap-0805-22uF/16V: (-55 to 85 DegC) CAP CER 22uF 16V X5R 0805; MfrNo: CL21A226MOQNNNE; Mfr: Samsung; PN: 1314; Alt: CL21A226MOCLRNC,CL21A226KOQNNNG,GRM21BR61C226ME44L,EMK212BBJ226MG-T
C16 = 0665-Cap-0603-470pF/50V: (-55 to 125 DegC) CAP CER 470PF 50V NP0 0603; MfrNo: CL10C471JB8NNNC; Mfr: Samsung Electro-Mechanics America, Inc.; Alt: CL10C471JB8NCNC; PN: 665; TR: 1276-1168-2-ND; DR: 1276-1168-6-ND
C17 C29 C34 C47 C48 = 1566-Cap-0402-100nF/50V: as C192-C197 on sheet 400_M2_KeyB
C18-C20 C23 C40 C43 C331 C332 = 1607-Cap-1206-10uF/50V: as C205 on sheet 420_MIPI_DSI
C21 C22 C24-C26 = 2404-Cap-0402-22uF/6.3V: (-55 to 85 DegC) CAP CER 22UF 6.3V 20% X5R 0402; MfrNo: GRM155R60J226ME11D; Mfr: Murata; PN: 2404
C27 = 1149-Cap-0402-10nF/50V: (-55 to 125 DegC) Cap Ceramic 10nF 50V X7R 10% 0402; Mfr: Yageo; MfrNo: CC0402KRX7R9BB103; PN: 1149; Alt: CL05B103KB5NNNC,UMK105BJ103KV-F,CL05B103KB5NFNC,0402B103K500CT,CC0402KRX7R9BB103
C30 = 2163-Cap-0603-10uF/16V: (-55 to 85 DegC) CAP CER 10UF 16V 10% X5R 0603; MfrNo: GRM21BR61C106KE15L; Mfr: Murata; PN: 2163; Desc: (-55 to 85 DegC) CAP CER 4.7UF 16V 10% X5R 0603
C36 = 0318-Cap-0402-1nF/50V: (-55 to 125 DegC) CAP CER 1000PF 50V 5% NP0 0402; Mfr: Samsung Electro-Mechanics America, Inc; MfrNo: CL05C102JB5NNNC; Alt: 399-10034-1-ND; Alt2: 490-3244-1-ND; PN: 318
C37 = 1567-Cap-0603-47pF/100V: (-55 to 125 DegC AEC) Cap Ceramic 47pF 100V C0G/NP0 5% SMD 0603; Mfr: Samsung; MfrNo: CL10C470JC81PNC; Alt: C0603C470J1GACAUTO,06031A470J4T2A,GCM1885C2A470JA16D; PN: 1567
C38 = 0213-Cap-0603-220pF/50V: (-55 to 125 DegC) CAP CER 220PF 50V 5% NP0 0603; Mfr: Samsung; MfrNo: CL10C221JB8NCNC; Alt: 1276-2231-1-ND; Alt2: 399-1066-1-ND; PN: 213; TR: 1276-2234-2-ND; DR: 1276-2234-6-ND
C42 C44-C46 = 1647-Cap-0805-47uF/10V: (-55 to 85 DegC) CAP CER 47UF 10V X5R 0805; MfrNo: GRM21BR61A476ME15L; Mfr: Murata; PN: 1647; Alt: LMK212BBJ476MG-T,GRM21BR61A476ME15K,C2012X5R1A476M125AC
C49 = 1644-Cap-0402-1uF/16V: as C213 on sheet 500_CAN
C50 = 0000-Cap-0603-DNP: Cap 0603 DNP
D6 D7 D48 = 0333-LED Green 0603: as D25 on sheet 400_M2_KeyB
D8 D15 = 1655-D5V0L1B2S9-7: (-65 to 155 DegC) TVS DIODE Vwm:5V Vcl:14V@6A SOD-923; Mfr: Diodes; PN: 1655
D9 = 0333-LED Green 0603: (-40 to 85 DegC) LED GREEN 0603 50mcd; Mfr: Kingbright; MfrNo: APT1608CGCK; Alt: 754-1357-1-ND; Alt2: 160-1834-1-ND; PN: 333; DR: 754-1116-6-ND; DR2: 604-APT1608CGCK
J47 = 2193-Conn-Hdr 2x3 2.54MM F: (-40 to 125 DegC) CONN HEADER FEMALE 2x3 6POS 2.54MM TH; Mfr: Wurth Electronics; PN: 2193
L4 L6 = 1845-Ind-8x8x5-4.7uH/11A: (-40 to 85 DegC) FIXED IND 4.7UH 11A Is:13A 14 mohm typ, 15.4 moh max SMD 8.4x8x5 full-shield; Mfr: Eaton Bussmann; PN: 1845; Note: Alt: PN1846
L5 = 1618-Ind-1210-1uH/5.5A: (-40 to 125 DegC) FIXED IND 1UH I:5.5A Isat:6.5A 32mohm max 26mohm typ, full-shield SMD 1210; MfrNo: SRP3212-1R0M; Mfr: Bourns; PN: 1618; Alt: DFE322512F-1R0M=P2,DFE32CAH1R0MR0L,DFE322520F-1R0M=P2,DFE322520FD-1R0M=P2
Q5 Q8 = 0761-FDV301N: as Q6 on sheet 400_M2_KeyB
Q7 = 1674-NTZD3155CT1G: (-40 to 85 DegC) MOSFET N/P-CH 20V 0.54/0.43A Vgs:1V SOT-563; Mfr: ON Semiconductor; PN: 1674
R27 R58 R59 = 1572-Res-0402-10K: as R181 on sheet 400_M2_KeyB
R28 R32 R33 R38 R64 = 0195-Res-0603-0.0ohm: as R183 on sheet 400_M2_KeyB
R29-R31 R36 R45 R55 = 1538-Res-0402-27k: as R182 on sheet 400_M2_KeyB
R34 = 0000-Res-0603-DNP: RES 0603
R35 R37 R53 R56 R57 = 1977-Res-0402-100K: (-55 to 155 DegC) RES 100K OHM 1/16W 1% 0402 SMD; Mfr: Yageo; MfrNo: RC0402FR-07100KL; PN: 1977
R39 = 0034-Res-1206-0.010: RES CURRENT SENSE .010 OHM 1W 1% 50ppm; Mfr: Ohmite; MfrNo: MCS1632R010FER; Alt: LVK12R010FERCT-ND; Alt2: CRF1206-FX-R010ELFCT-ND; PN: 34
R40 R60 R430 R465 = 2233-Res-0402-4.7K: (-55 to 155 DegC) RES 4.70K OHM 1/16W 1% 0402 100ppm; MfrNo: RC0402FR-074K7L; Mfr: Yageo; PN: 2233
R41 R42 R48 = 0866-Res-0603-220K: (-55 to 155 DegC) RES SMD 220K OHM 1% 1/10W 0603; Mfr: Yageo; MfrNo: RC0603FR-07220KL; Alt: ERJ-3EKF2203V; PN: 866; Alt2: RMCF0603FT220K; Desc: (-55 to 155 DegC AEC) RES SMD 2.4 OHM 1% 1/10W 0603 100ppm
R44 R49 = 1144-Res-0603-24.9K: (-55 to 155 DegC) RES SMD 24.9K OHM 1% 1/10W 0603 100ppm; MfrNo: RMCF0603FT24K9; Mfr: Stackpole Electronics; Alt: CR0603-FX-2492ELF,RC0603FR-0724K9L; PN: 1144
R46 = 1216-Res-0603-20K: (-55 to 155 DegC) RES SMD 20K 1% 1/10W 0603 100ppm; Mfr: Bourns; MfrNo: CR0603-FX-2002ELF; Alt: RMCF0603FT20K0,CR0603-FX-2002ELF,RK73H1JTTD2002F,RC0603FR-0720KL; PN: 1216
R47 = 1550-Res-0402-15K: (-55 to 155 DegC AEC) RES 15K OHM 1% 1/16W 100ppm 0402; Mfr: Stackpole Electronics; MfrNo: RMCF0402FT15K0; Alt: AC0402FR-0715KL,CRGCQ0402F15K; PN: 1550
R51 = 0034-Res-1206-0.010: (-55 to 150 DegC) RES CURRENT SENSE .010 OHM 1W 1% 50ppm; Mfr: Ohmite; MfrNo: MCS1632R010FER; Alt: LVK12R010FERCT-ND; Alt2: CRF1206-FX-R010ELFCT-ND; PN: 34
R52 = 1536-Res-0402-1.87K: as R187 on sheet 400_M2_KeyB
R54 = 0195-Res-0603-0.0ohm: (-55 to 155 DegC) RES 0.0 OHM 1/10W JUMP 0603; Mfr: Samsung; MfrNo: RC1608J000CS; PN: 195; TR: 1276-3510-2-ND; Alt: 311-0.0GRCT-ND; Alt2: A106051CT-ND
U5 = 1619-TPS62823: (-40 to 125 DegC) IC  IC REG BUCK ADJ 2.2MHz Vin:2.4-5.5V Io:3A Sync 8-VFDFN 8VSON-HR; Mfr: Texas Instruments; PN: 1619; Alt: TPS62823DLCT; Note: similar with smaller output current: TPS62822DLC, TPS62821DLC
U6 = 1815-AOZ2261AQI-15: (-40 to 85 DegC) 8A Syncronous Buck Regulator (Auto Restart), QFN4x4-22L, 4-28V; Mfr: Alpha & Omega Semiconductor; PN: 1815
U7 = 2218-TPS61089RNRR: (-40 to 85 DegC) IC REG BOOST ADJ 7A SYNC 20VQFN Vin:2.7-12V, Vout:4.5-12.6V 11VQFN; Mfr: Texas Instruments; PN: 2218
U8 = 2192-LTC2954CTS8-2#TRMPBF: (0 to 70 DegC) IC PB ON/OFF CONTROLLER TSOT23-8; Mfr: Analog Devices / Linear Technology; PN: 2192
X13-X15 X18 X19 X21-X24 X28 = 000-TestPoint: as X63 on sheet 400_M2_KeyB
X17 X20 = 000-TestPoint2: as X27 on sheet 400_M2_KeyB

## Sheet 140_Power_3.SchDoc: Aquila Development Board
size Letter; Organization: Toradex Solutions Inc.; Address1: 6415 Northwest Drive; Address2: Mississauga, ON, L4V 1X1; Address3: Canada; SheetNumber: 5; SheetTotal: 34
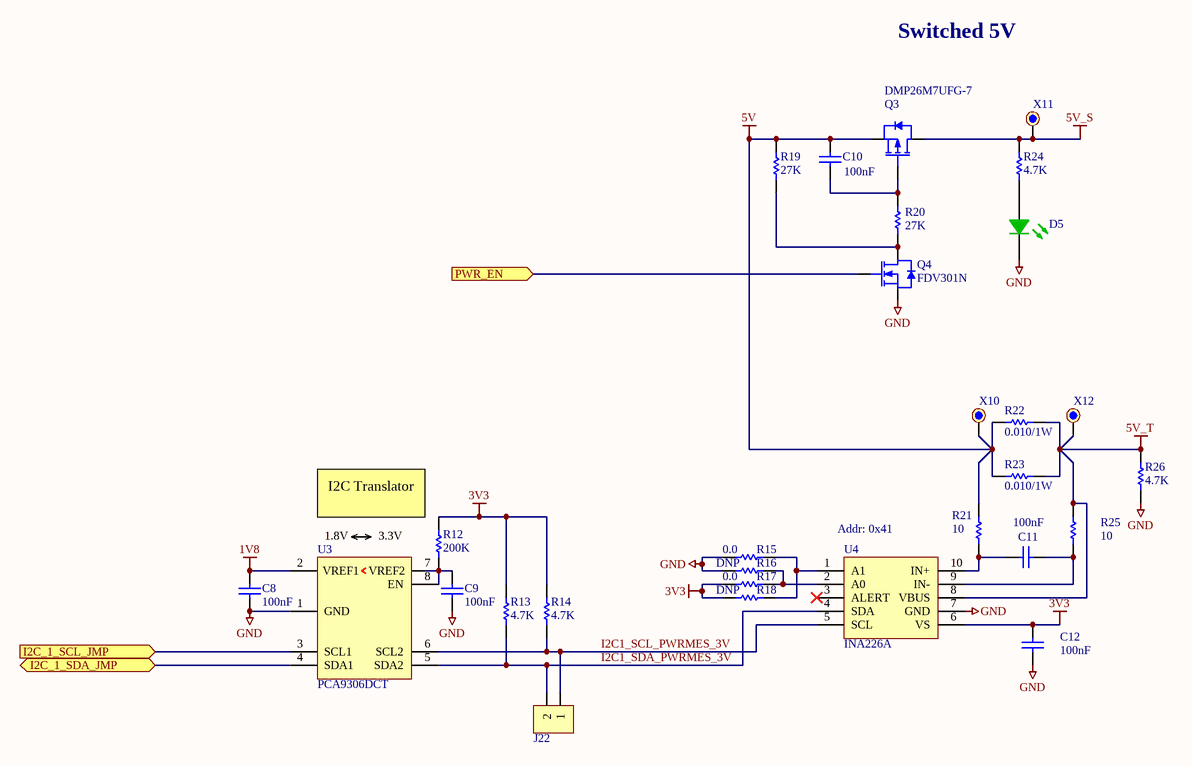
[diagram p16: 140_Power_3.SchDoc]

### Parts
C8  100nF  [C0402_CAPC1005L]
C9  100nF  [C0402_CAPC1005L]
C10  100nF  [C0402_CAPC1005L]
C11  100nF  [C0402_CAPC1005L]
C12  100nF  [C0402_CAPC1005L]
D5  Status  [LED-SMT-0603_APT1608CGCK]  (value not drawn)
J22  000-Hdr-2pin  [HDR1X2]  (value not drawn)  (no BOM)
Q3  DMP26M7UFG-7  [DMP3008]
Q4  FDV301N  [SOT23]
R12  value 200K  [R0402_RESC1005L]  (hidden comment: 1540-Res-0402-200k)
R13  value 4.7K  [R0402_RESC1005L]  (hidden comment: 2233-Res-0402-4.7K)
R14  value 4.7K  [R0402_RESC1005L]  (hidden comment: 2233-Res-0402-4.7K)
R15  value 0.0  [R/0603]  (hidden comment: 0195-Res-0603-0.0ohm)
R16  value DNP  [R/0603]  (hidden comment: 0000-Res-0603-DNP)
R17  value 0.0  [R/0603]  (hidden comment: 0195-Res-0603-0.0ohm)
R18  value DNP  [R/0603]  (hidden comment: 0000-Res-0603-DNP)
R19  value 27K  [R0402_RESC1005L]  (hidden comment: 1538-Res-0402-27k)
R20  value 27K  [R0402_RESC1005L]  (hidden comment: 1538-Res-0402-27k)
R21  value 10  [R0402_RESC1005L]  (hidden comment: 0257-Res-0402-10ohm)
R22  value 0.010/1W  [R/1206]  (hidden comment: 0034-Res-1206-0.010)
R23  value 0.010/1W  [R/1206]  (hidden comment: 0034-Res-1206-0.010)
R24  value 4.7K  [R0402_RESC1005L]  (hidden comment: 2233-Res-0402-4.7K)
R25  value 10  [R0402_RESC1005L]  (hidden comment: 0257-Res-0402-10ohm)
R26  value 4.7K  [R0402_RESC1005L]  (hidden comment: 2233-Res-0402-4.7K)
U3  PCA9306DCT  [TSSO3x5-G8/X.35]
U4  INA226A  [MSOP-10]
X10  000-TestPoint  [TestPoint_1]  (value not drawn)
X11  000-TestPoint  [TestPoint_1]  (value not drawn)
X12  000-TestPoint  [TestPoint_1]  (value not drawn)

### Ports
I2C_1_SCL_JMP (in), I2C_1_SDA_JMP (bidir), PWR_EN (in)

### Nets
1V8: C8.2 U3.2(VREF1)
3V3: C12.2 R12.1 R13.1 R14.1 R17.1 R18.1 U4.6(VS)
5V: C10.2 Q3.S R19.2 R21.2 R22.1 R23.1 X10.1
5V_S: Q3.D R24.2 X11.1
5V_T: R22.2 R23.2 R25.2 R26.2 U4.8(VBUS) X12.1
GND: C8.1 C9.1 C12.1 D5.2(K) Q4.2(S) R15.1 R16.1 R26.1 U3.1(GND) U4.7(GND)
I2C1_SCL_PWRMES_3V: J22.1 R14.2 U3.6(SCL2) U4.5(SCL)
I2C1_SDA_PWRMES_3V: J22.2 R13.2 U3.5(SDA2) U4.4(SDA)
I2C_1_SCL_JMP: U3.3(SCL1) ; port I2C_1_SCL_JMP
I2C_1_SDA_JMP: U3.4(SDA1) ; port I2C_1_SDA_JMP
PWR_EN: Q4.1(G) ; port PWR_EN
NetC9_2: C9.2 R12.2 U3.7(VREF2) U3.8(EN)
NetC10_1: C10.1 Q3.G R20.2
NetC11_1: C11.1 R25.1 U4.9(IN-)
NetC11_2: C11.2 R21.1 U4.10(IN+)
NetD5_1: D5.1(A) R24.1
NetQ4_3: Q4.3(D) R19.1 R20.1
NetR15_2: R15.2 R18.2 U4.1(A1)
NetR16_2: R16.2 R17.2 U4.2(A0)

Not connected (* = marked no-connect by the designer): U4 3(ALERT)*

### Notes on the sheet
- Switched 5V
- (near R12) I2C Translator
- (near U3) 1.8V
- 3.3V
- (near U4) Addr: 0x41

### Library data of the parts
C8-C12 = 1566-Cap-0402-100nF/50V: as C192-C197 on sheet 400_M2_KeyB
D5 = 0333-LED Green 0603: as D25 on sheet 400_M2_KeyB
J22 = 000-Hdr-2pin: Header, 2-Pin; Note: PCB footprint only, no parts to buy or assemble
Q3 = 1858-DMP26M7UFG-7: (-55 to 150 DegC) MOSFET P-CH 20V 18A 4.2mohm@4.5V 7mohm@1.8V Vgsm:10V 3x3mm POWERDI3333; Mfr: Diodes; PN: 1858; Alt: DMP26M7UFG-13
Q4 = 0761-FDV301N: as Q6 on sheet 400_M2_KeyB
R12 = 1540-Res-0402-200k: (-55 to 155 DegC AEC) RES 200K OHM 1% 1/16W 100ppm 0402; Mfr: Stackpole Electronics; MfrNo: RMCF0402FT200K; Alt: AC0402FR-07200KL,AC0402FR-7W200KL,ERJ-2RKF2003X; PN: 1540
R13 R14 R24 R26 = 2233-Res-0402-4.7K: as R40 on sheet 120_Power_2
R15 R17 = 0195-Res-0603-0.0ohm: as R183 on sheet 400_M2_KeyB
R16 R18 = 0000-Res-0603-DNP: RES 0603
R19 R20 = 1538-Res-0402-27k: as R182 on sheet 400_M2_KeyB
R21 R25 = 0257-Res-0402-10ohm: (-55 to 155 DegC) RES 10 OHM 1/16W 1% 0402 SMD; Mfr: Rohm Semiconductor; MfrNo: MCR01MRTF10R0; Alt: 311-10.0LRCT-ND; Alt2: 1276-3428-1-ND; PN: 257
R22 R23 = 0034-Res-1206-0.010: as R51 on sheet 120_Power_2
U3 = 0972-PCA9306DCT: (-40 to 85 DegC) IC TRANSLTR BIDIRECTIONAL I2C SM8; MfrNo: PCA9306DCTR; Mfr: Texas Instruments; PN: 972
U4 = 0966-INA226AIDGSR: (-40 to 125 DegC) IC MONITOR PWR/CURR BIDIR 10MSOP I2C Vos:10uV max, 0.1%Gain Err max, 2.7-5.5Vcc, 0-36V; Mfr: Texas Instruments; PN: 966
X10-X12 = 000-TestPoint: as X63 on sheet 400_M2_KeyB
